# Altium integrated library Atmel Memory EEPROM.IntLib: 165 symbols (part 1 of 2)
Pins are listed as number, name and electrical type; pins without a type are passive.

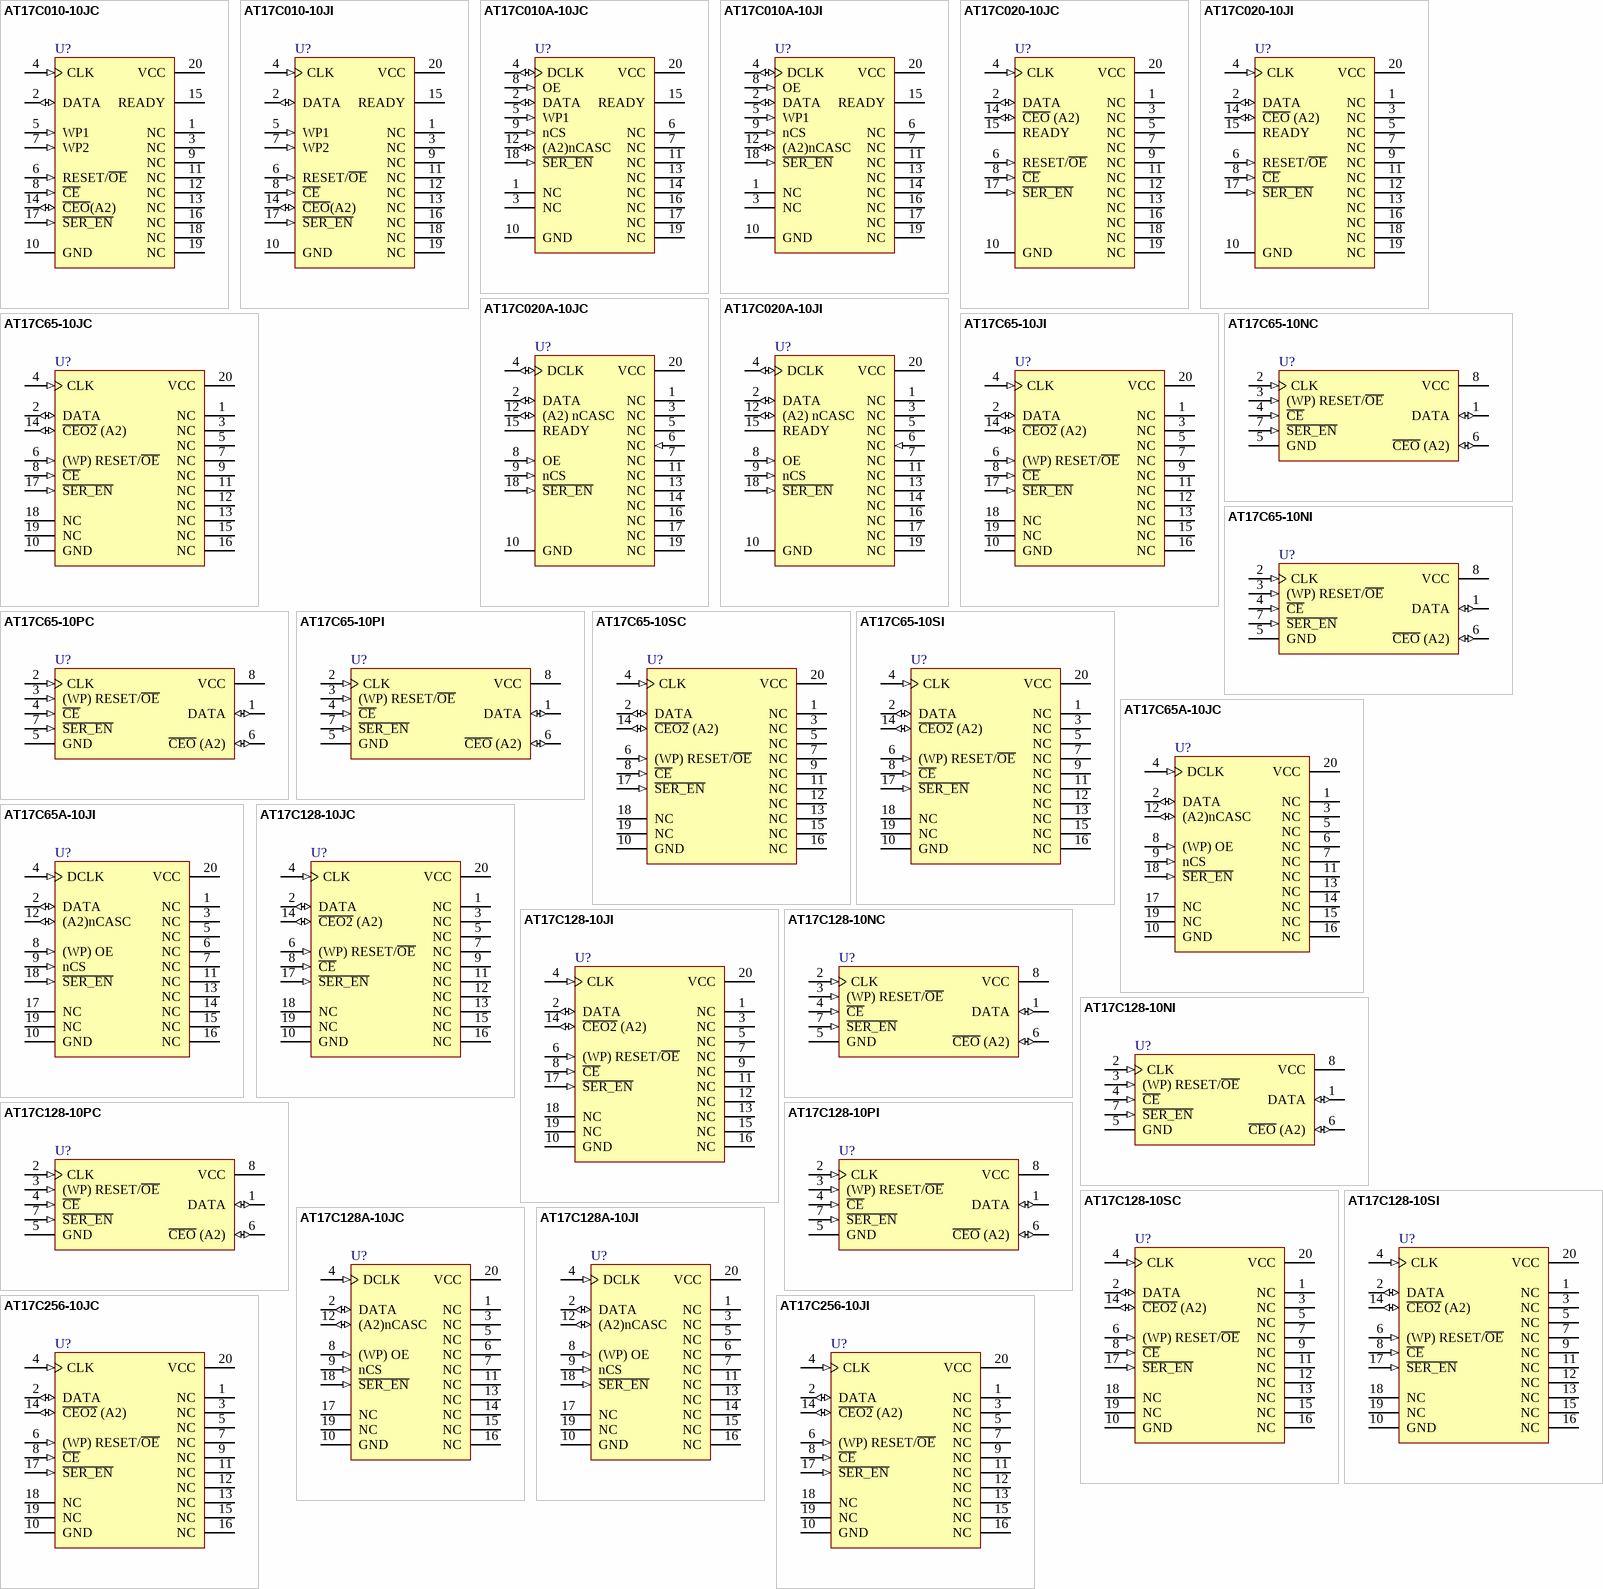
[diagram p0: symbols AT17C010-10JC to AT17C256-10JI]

## AT17C010-10JC
designator U?
FPGA Configuration EEPROM 1M Memory; ComponentAvailability: Not Recommended for New Design
footprint 20J_N (Leaded Chip Carrier, 20-Leads, Body 9x9mm, Pitch 1.27mm, IPC Medium Density)
footprint 20J_L (Leaded Chip Carrier, 20-Leads, Body 9x9mm, Pitch 1.27mm, IPC High Density)
footprint 20J_M (Leaded Chip Carrier, 20-Leads, Body 9x9mm, Pitch 1.27mm, IPC Low Density)
pins: 1 NC, 2 DATA (io), 3 NC, 4 CLK (in), 5 WP1 (in), 6 RESET/~{OE} (in), 7 WP2 (in), 8 ~{CE} (in), 9 NC, 10 GND (power), 11 NC, 12 NC, 13 NC, 14 ~{CEO}(A2) (io), 15 READY (oc), 16 NC, 17 ~{SER_EN} (in), 18 NC, 19 NC, 20 VCC (power)

## AT17C010-10JI
designator U?
FPGA Configuration EEPROM 1M Memory; ComponentAvailability: Not Recommended for New Design
footprint 20J_N (Leaded Chip Carrier, 20-Leads, Body 9x9mm, Pitch 1.27mm, IPC Medium Density)
footprint 20J_L (Leaded Chip Carrier, 20-Leads, Body 9x9mm, Pitch 1.27mm, IPC High Density)
footprint 20J_M (Leaded Chip Carrier, 20-Leads, Body 9x9mm, Pitch 1.27mm, IPC Low Density)
pins: 1 NC, 2 DATA (io), 3 NC, 4 CLK (in), 5 WP1 (in), 6 RESET/~{OE} (in), 7 WP2 (in), 8 ~{CE} (in), 9 NC, 10 GND (power), 11 NC, 12 NC, 13 NC, 14 ~{CEO}(A2) (io), 15 READY (oc), 16 NC, 17 ~{SER_EN} (in), 18 NC, 19 NC, 20 VCC (power)

## AT17C010A-10JC
designator U?
FPGA Configuration EEPROM  1M Memory; ComponentAvailability: Not Recommended for New Design
footprint 20J_N (Leaded Chip Carrier, 20-Leads, Body 9x9mm, Pitch 1.27mm, IPC Medium Density)
footprint 20J_L (Leaded Chip Carrier, 20-Leads, Body 9x9mm, Pitch 1.27mm, IPC High Density)
footprint 20J_M (Leaded Chip Carrier, 20-Leads, Body 9x9mm, Pitch 1.27mm, IPC Low Density)
pins: 1 NC, 2 DATA (io), 3 NC, 4 DCLK (io), 5 WP1 (in), 6 NC, 7 NC, 8 OE (in), 9 nCS (in), 10 GND (power), 11 NC, 12 (A2)nCASC (io), 13 NC, 14 NC, 15 READY (oc), 16 NC, 17 NC, 18 ~{SER_EN} (in), 19 NC, 20 VCC (power)

## AT17C010A-10JI
designator U?
FPGA Configuration EEPROM  1M Memory; ComponentAvailability: Not Recommended for New Design
footprint 20J_N (Leaded Chip Carrier, 20-Leads, Body 9x9mm, Pitch 1.27mm, IPC Medium Density)
footprint 20J_L (Leaded Chip Carrier, 20-Leads, Body 9x9mm, Pitch 1.27mm, IPC High Density)
footprint 20J_M (Leaded Chip Carrier, 20-Leads, Body 9x9mm, Pitch 1.27mm, IPC Low Density)
pins: 1 NC, 2 DATA (io), 3 NC, 4 DCLK (io), 5 WP1 (in), 6 NC, 7 NC, 8 OE (in), 9 nCS (in), 10 GND (power), 11 NC, 12 (A2)nCASC (io), 13 NC, 14 NC, 15 READY (oc), 16 NC, 17 NC, 18 ~{SER_EN} (in), 19 NC, 20 VCC (power)

## AT17C020-10JC
designator U?
FPGA Configuration EEPROM 2M Memory; ComponentAvailability: Not Recommended for New Design
footprint 20J_N (Leaded Chip Carrier, 20-Leads, Body 9x9mm, Pitch 1.27mm, IPC Medium Density)
footprint 20J_L (Leaded Chip Carrier, 20-Leads, Body 9x9mm, Pitch 1.27mm, IPC High Density)
footprint 20J_M (Leaded Chip Carrier, 20-Leads, Body 9x9mm, Pitch 1.27mm, IPC Low Density)
pins: 1 NC, 2 DATA (io), 3 NC, 4 CLK (in), 5 NC, 6 RESET/~{OE} (in), 7 NC, 8 ~{CE} (in), 9 NC, 10 GND (power), 11 NC, 12 NC, 13 NC, 14 ~{CEO} (A2) (io), 15 READY (oc), 16 NC, 17 ~{SER_EN} (in), 18 NC, 19 NC, 20 VCC (power)

## AT17C020-10JI
designator U?
FPGA Configuration EEPROM 2M Memory; ComponentAvailability: Not Recommended for New Design
footprint 20J_N (Leaded Chip Carrier, 20-Leads, Body 9x9mm, Pitch 1.27mm, IPC Medium Density)
footprint 20J_L (Leaded Chip Carrier, 20-Leads, Body 9x9mm, Pitch 1.27mm, IPC High Density)
footprint 20J_M (Leaded Chip Carrier, 20-Leads, Body 9x9mm, Pitch 1.27mm, IPC Low Density)
pins: 1 NC, 2 DATA (io), 3 NC, 4 CLK (in), 5 NC, 6 RESET/~{OE} (in), 7 NC, 8 ~{CE} (in), 9 NC, 10 GND (power), 11 NC, 12 NC, 13 NC, 14 ~{CEO} (A2) (io), 15 READY (oc), 16 NC, 17 ~{SER_EN} (in), 18 NC, 19 NC, 20 VCC (power)

## AT17C020A-10JC
designator U?
FPGA Configuration EEPROM 2M Memory; ComponentAvailability: Not Recommended for New Design
footprint 20J_N (Leaded Chip Carrier, 20-Leads, Body 9x9mm, Pitch 1.27mm, IPC Medium Density)
footprint 20J_L (Leaded Chip Carrier, 20-Leads, Body 9x9mm, Pitch 1.27mm, IPC High Density)
footprint 20J_M (Leaded Chip Carrier, 20-Leads, Body 9x9mm, Pitch 1.27mm, IPC Low Density)
pins: 1 NC, 2 DATA (io), 3 NC, 4 DCLK (io), 5 NC, 6 NC (in), 7 NC, 8 OE (in), 9 nCS (in), 10 GND (power), 11 NC, 12 (A2) nCASC (io), 13 NC, 14 NC, 15 READY (oc), 16 NC, 17 NC, 18 ~{SER_EN} (in), 19 NC, 20 VCC (power)

## AT17C020A-10JI
designator U?
FPGA Configuration EEPROM 2M Memory; ComponentAvailability: Not Recommended for New Design
footprint 20J_N (Leaded Chip Carrier, 20-Leads, Body 9x9mm, Pitch 1.27mm, IPC Medium Density)
footprint 20J_L (Leaded Chip Carrier, 20-Leads, Body 9x9mm, Pitch 1.27mm, IPC High Density)
footprint 20J_M (Leaded Chip Carrier, 20-Leads, Body 9x9mm, Pitch 1.27mm, IPC Low Density)
pins: 1 NC, 2 DATA (io), 3 NC, 4 DCLK (io), 5 NC, 6 NC (in), 7 NC, 8 OE (in), 9 nCS (in), 10 GND (power), 11 NC, 12 (A2) nCASC (io), 13 NC, 14 NC, 15 READY (oc), 16 NC, 17 NC, 18 ~{SER_EN} (in), 19 NC, 20 VCC (power)

## AT17C65-10JC
designator U?
FPGA Configuration EEPROM 64K Memory; ComponentAvailability: Not Recommended for New Design
footprint 20J_N (Leaded Chip Carrier, 20-Leads, Body 9x9mm, Pitch 1.27mm, IPC Medium Density)
footprint 20J_L (Leaded Chip Carrier, 20-Leads, Body 9x9mm, Pitch 1.27mm, IPC High Density)
footprint 20J_M (Leaded Chip Carrier, 20-Leads, Body 9x9mm, Pitch 1.27mm, IPC Low Density)
pins: 1 NC, 2 DATA (io), 3 NC, 4 CLK (in), 5 NC, 6 (WP) RESET/~{OE} (in), 7 NC, 8 ~{CE} (in), 9 NC, 10 GND (power), 11 NC, 12 NC, 13 NC, 14 ~{CEO2} (A2) (io), 15 NC, 16 NC, 17 ~{SER_EN} (in), 18 NC, 19 NC, 20 VCC (power)

## AT17C65-10JI
designator U?
FPGA Configuration EEPROM 64K Memory; ComponentAvailability: Not Recommended for New Design
footprint 20J_N (Leaded Chip Carrier, 20-Leads, Body 9x9mm, Pitch 1.27mm, IPC Medium Density)
footprint 20J_L (Leaded Chip Carrier, 20-Leads, Body 9x9mm, Pitch 1.27mm, IPC High Density)
footprint 20J_M (Leaded Chip Carrier, 20-Leads, Body 9x9mm, Pitch 1.27mm, IPC Low Density)
pins: 1 NC, 2 DATA (io), 3 NC, 4 CLK (in), 5 NC, 6 (WP) RESET/~{OE} (in), 7 NC, 8 ~{CE} (in), 9 NC, 10 GND (power), 11 NC, 12 NC, 13 NC, 14 ~{CEO2} (A2) (io), 15 NC, 16 NC, 17 ~{SER_EN} (in), 18 NC, 19 NC, 20 VCC (power)

## AT17C65-10NC
designator U?
FPGA Configuration EEPROM 64K Memory; ComponentAvailability: Not Recommended for New Design
footprint 8S1_N (SOIC, 8-Leads, Body 4.9x3.9mm, Pitch 1.27mm, IPC Medium Density)
footprint 8S1_L (SOIC, 8-Leads, Body 4.9x3.9mm, Pitch 1.27mm, IPC High Density)
footprint 8S1_M (SOIC, 8-Leads, Body 4.9x3.9mm, Pitch 1.27mm, IPC Low Density)
pins: 1 DATA (io), 2 CLK (in), 3 (WP) RESET/~{OE} (in), 4 ~{CE} (in), 5 GND (power), 6 ~{CEO} (A2) (io), 7 ~{SER_EN} (in), 8 VCC (power)

## AT17C65-10NI
designator U?
FPGA Configuration EEPROM 64K Memory; ComponentAvailability: Not Recommended for New Design
footprint 8S1_N (SOIC, 8-Leads, Body 4.9x3.9mm, Pitch 1.27mm, IPC Medium Density)
footprint 8S1_L (SOIC, 8-Leads, Body 4.9x3.9mm, Pitch 1.27mm, IPC High Density)
footprint 8S1_M (SOIC, 8-Leads, Body 4.9x3.9mm, Pitch 1.27mm, IPC Low Density)
pins: 1 DATA (io), 2 CLK (in), 3 (WP) RESET/~{OE} (in), 4 ~{CE} (in), 5 GND (power), 6 ~{CEO} (A2) (io), 7 ~{SER_EN} (in), 8 VCC (power)

## AT17C65-10PC
designator U?
FPGA Configuration EEPROM 64K Memory; ComponentAvailability: Not Recommended for New Design
footprint 8P3 (DIP, 8-Leads, Row Spacing 7.62mm, Pitch 2.54mm, Body 9.59x6.61mm)
pins: 1 DATA (io), 2 CLK (in), 3 (WP) RESET/~{OE} (in), 4 ~{CE} (in), 5 GND (power), 6 ~{CEO} (A2) (io), 7 ~{SER_EN} (in), 8 VCC (power)

## AT17C65-10PI
designator U?
FPGA Configuration EEPROM 64K Memory; ComponentAvailability: Not Recommended for New Design
footprint 8P3 (DIP, 8-Leads, Row Spacing 7.62mm, Pitch 2.54mm, Body 9.59x6.61mm)
pins: 1 DATA (io), 2 CLK (in), 3 (WP) RESET/~{OE} (in), 4 ~{CE} (in), 5 GND (power), 6 ~{CEO} (A2) (io), 7 ~{SER_EN} (in), 8 VCC (power)

## AT17C65-10SC
designator U?
FPGA Configuration EEPROM 64K Memory; ComponentAvailability: Not Recommended for New Design
footprint 20S_N (SOIC, 20-Leads, Body 12.8x7.5mm, Pitch 1.27mm, IPC Medium Density)
footprint 20S_L (SOIC, 20-Leads, Body 12.8x7.5mm, Pitch 1.27mm, IPC High Density)
footprint 20S_M (SOIC, 20-Leads, Body 12.8x7.5mm, Pitch 1.27mm, IPC Low Density)
pins: 1 NC, 2 DATA (io), 3 NC, 4 CLK (in), 5 NC, 6 (WP) RESET/~{OE} (in), 7 NC, 8 ~{CE} (in), 9 NC, 10 GND (power), 11 NC, 12 NC, 13 NC, 14 ~{CEO2} (A2) (io), 15 NC, 16 NC, 17 ~{SER_EN} (in), 18 NC, 19 NC, 20 VCC (power)

## AT17C65-10SI
designator U?
FPGA Configuration EEPROM 64K Memory; ComponentAvailability: Not Recommended for New Design
footprint 20S_N (SOIC, 20-Leads, Body 12.8x7.5mm, Pitch 1.27mm, IPC Medium Density)
footprint 20S_L (SOIC, 20-Leads, Body 12.8x7.5mm, Pitch 1.27mm, IPC High Density)
footprint 20S_M (SOIC, 20-Leads, Body 12.8x7.5mm, Pitch 1.27mm, IPC Low Density)
pins: 1 NC, 2 DATA (io), 3 NC, 4 CLK (in), 5 NC, 6 (WP) RESET/~{OE} (in), 7 NC, 8 ~{CE} (in), 9 NC, 10 GND (power), 11 NC, 12 NC, 13 NC, 14 ~{CEO2} (A2) (io), 15 NC, 16 NC, 17 ~{SER_EN} (in), 18 NC, 19 NC, 20 VCC (power)

## AT17C65A-10JC
designator U?
FPGA Configuration EEPROM 64K Memory; ComponentAvailability: Not Recommended for New Design
footprint 20J_N (Leaded Chip Carrier, 20-Leads, Body 9x9mm, Pitch 1.27mm, IPC Medium Density)
footprint 20J_L (Leaded Chip Carrier, 20-Leads, Body 9x9mm, Pitch 1.27mm, IPC High Density)
footprint 20J_M (Leaded Chip Carrier, 20-Leads, Body 9x9mm, Pitch 1.27mm, IPC Low Density)
pins: 1 NC, 2 DATA (io), 3 NC, 4 DCLK (in), 5 NC, 6 NC, 7 NC, 8 (WP) OE (in), 9 nCS (in), 10 GND (power), 11 NC, 12 (A2)nCASC (io), 13 NC, 14 NC, 15 NC, 16 NC, 17 NC, 18 ~{SER_EN} (in), 19 NC, 20 VCC (power)

## AT17C65A-10JI
designator U?
FPGA Configuration EEPROM 64K Memory; ComponentAvailability: Not Recommended for New Design
footprint 20J_N (Leaded Chip Carrier, 20-Leads, Body 9x9mm, Pitch 1.27mm, IPC Medium Density)
footprint 20J_L (Leaded Chip Carrier, 20-Leads, Body 9x9mm, Pitch 1.27mm, IPC High Density)
footprint 20J_M (Leaded Chip Carrier, 20-Leads, Body 9x9mm, Pitch 1.27mm, IPC Low Density)
pins: 1 NC, 2 DATA (io), 3 NC, 4 DCLK (in), 5 NC, 6 NC, 7 NC, 8 (WP) OE (in), 9 nCS (in), 10 GND (power), 11 NC, 12 (A2)nCASC (io), 13 NC, 14 NC, 15 NC, 16 NC, 17 NC, 18 ~{SER_EN} (in), 19 NC, 20 VCC (power)

## AT17C128-10JC
designator U?
FPGA Configuration EEPROM 128K Memory; ComponentAvailability: Not Recommended for New Design
footprint 20J_N (Leaded Chip Carrier, 20-Leads, Body 9x9mm, Pitch 1.27mm, IPC Medium Density)
footprint 20J_L (Leaded Chip Carrier, 20-Leads, Body 9x9mm, Pitch 1.27mm, IPC High Density)
footprint 20J_M (Leaded Chip Carrier, 20-Leads, Body 9x9mm, Pitch 1.27mm, IPC Low Density)
pins: 1 NC, 2 DATA (io), 3 NC, 4 CLK (in), 5 NC, 6 (WP) RESET/~{OE} (in), 7 NC, 8 ~{CE} (in), 9 NC, 10 GND (power), 11 NC, 12 NC, 13 NC, 14 ~{CEO2} (A2) (io), 15 NC, 16 NC, 17 ~{SER_EN} (in), 18 NC, 19 NC, 20 VCC (power)

## AT17C128-10JI
designator U?
FPGA Configuration EEPROM 128K Memory; ComponentAvailability: Not Recommended for New Design
footprint 20J_N (Leaded Chip Carrier, 20-Leads, Body 9x9mm, Pitch 1.27mm, IPC Medium Density)
footprint 20J_L (Leaded Chip Carrier, 20-Leads, Body 9x9mm, Pitch 1.27mm, IPC High Density)
footprint 20J_M (Leaded Chip Carrier, 20-Leads, Body 9x9mm, Pitch 1.27mm, IPC Low Density)
pins: 1 NC, 2 DATA (io), 3 NC, 4 CLK (in), 5 NC, 6 (WP) RESET/~{OE} (in), 7 NC, 8 ~{CE} (in), 9 NC, 10 GND (power), 11 NC, 12 NC, 13 NC, 14 ~{CEO2} (A2) (io), 15 NC, 16 NC, 17 ~{SER_EN} (in), 18 NC, 19 NC, 20 VCC (power)

## AT17C128-10NC
designator U?
FPGA Configuration EEPROM 128K Memory; ComponentAvailability: Not Recommended for New Design
footprint 8S1_N (SOIC, 8-Leads, Body 4.9x3.9mm, Pitch 1.27mm, IPC Medium Density)
footprint 8S1_L (SOIC, 8-Leads, Body 4.9x3.9mm, Pitch 1.27mm, IPC High Density)
footprint 8S1_M (SOIC, 8-Leads, Body 4.9x3.9mm, Pitch 1.27mm, IPC Low Density)
pins: 1 DATA (io), 2 CLK (in), 3 (WP) RESET/~{OE} (in), 4 ~{CE} (in), 5 GND (power), 6 ~{CEO} (A2) (io), 7 ~{SER_EN} (in), 8 VCC (power)

## AT17C128-10NI
designator U?
FPGA Configuration EEPROM 128K Memory; ComponentAvailability: Not Recommended for New Design
footprint 8S1_N (SOIC, 8-Leads, Body 4.9x3.9mm, Pitch 1.27mm, IPC Medium Density)
footprint 8S1_L (SOIC, 8-Leads, Body 4.9x3.9mm, Pitch 1.27mm, IPC High Density)
footprint 8S1_M (SOIC, 8-Leads, Body 4.9x3.9mm, Pitch 1.27mm, IPC Low Density)
pins: 1 DATA (io), 2 CLK (in), 3 (WP) RESET/~{OE} (in), 4 ~{CE} (in), 5 GND (power), 6 ~{CEO} (A2) (io), 7 ~{SER_EN} (in), 8 VCC (power)

## AT17C128-10PC
designator U?
FPGA Configuration EEPROM 128K Memory; ComponentAvailability: Not Recommended for New Design
footprint 8P3 (DIP, 8-Leads, Row Spacing 7.62mm, Pitch 2.54mm, Body 9.59x6.61mm)
pins: 1 DATA (io), 2 CLK (in), 3 (WP) RESET/~{OE} (in), 4 ~{CE} (in), 5 GND (power), 6 ~{CEO} (A2) (io), 7 ~{SER_EN} (in), 8 VCC (power)

## AT17C128-10PI
designator U?
FPGA Configuration EEPROM 128K Memory; ComponentAvailability: Not Recommended for New Design
footprint 8P3 (DIP, 8-Leads, Row Spacing 7.62mm, Pitch 2.54mm, Body 9.59x6.61mm)
pins: 1 DATA (io), 2 CLK (in), 3 (WP) RESET/~{OE} (in), 4 ~{CE} (in), 5 GND (power), 6 ~{CEO} (A2) (io), 7 ~{SER_EN} (in), 8 VCC (power)

## AT17C128-10SC
designator U?
FPGA Configuration EEPROM 128K Memory; ComponentAvailability: Not Recommended for New Design
footprint 20S_N (SOIC, 20-Leads, Body 12.8x7.5mm, Pitch 1.27mm, IPC Medium Density)
footprint 20S_L (SOIC, 20-Leads, Body 12.8x7.5mm, Pitch 1.27mm, IPC High Density)
footprint 20S_M (SOIC, 20-Leads, Body 12.8x7.5mm, Pitch 1.27mm, IPC Low Density)
pins: 1 NC, 2 DATA (io), 3 NC, 4 CLK (in), 5 NC, 6 (WP) RESET/~{OE} (in), 7 NC, 8 ~{CE} (in), 9 NC, 10 GND (power), 11 NC, 12 NC, 13 NC, 14 ~{CEO2} (A2) (io), 15 NC, 16 NC, 17 ~{SER_EN} (in), 18 NC, 19 NC, 20 VCC (power)

## AT17C128-10SI
designator U?
FPGA Configuration EEPROM 128K Memory; ComponentAvailability: Not Recommended for New Design
footprint 20S_N (SOIC, 20-Leads, Body 12.8x7.5mm, Pitch 1.27mm, IPC Medium Density)
footprint 20S_L (SOIC, 20-Leads, Body 12.8x7.5mm, Pitch 1.27mm, IPC High Density)
footprint 20S_M (SOIC, 20-Leads, Body 12.8x7.5mm, Pitch 1.27mm, IPC Low Density)
pins: 1 NC, 2 DATA (io), 3 NC, 4 CLK (in), 5 NC, 6 (WP) RESET/~{OE} (in), 7 NC, 8 ~{CE} (in), 9 NC, 10 GND (power), 11 NC, 12 NC, 13 NC, 14 ~{CEO2} (A2) (io), 15 NC, 16 NC, 17 ~{SER_EN} (in), 18 NC, 19 NC, 20 VCC (power)

## AT17C128A-10JC
designator U?
FPGA Configuration EEPROM 128K Memory; ComponentAvailability: Not Recommended for New Design
footprint 20J_N (Leaded Chip Carrier, 20-Leads, Body 9x9mm, Pitch 1.27mm, IPC Medium Density)
footprint 20J_L (Leaded Chip Carrier, 20-Leads, Body 9x9mm, Pitch 1.27mm, IPC High Density)
footprint 20J_M (Leaded Chip Carrier, 20-Leads, Body 9x9mm, Pitch 1.27mm, IPC Low Density)
pins: 1 NC, 2 DATA (io), 3 NC, 4 DCLK (in), 5 NC, 6 NC, 7 NC, 8 (WP) OE (in), 9 nCS (in), 10 GND (power), 11 NC, 12 (A2)nCASC (io), 13 NC, 14 NC, 15 NC, 16 NC, 17 NC, 18 ~{SER_EN} (in), 19 NC, 20 VCC (power)

## AT17C128A-10JI
designator U?
FPGA Configuration EEPROM 128K Memory; ComponentAvailability: Not Recommended for New Design
footprint 20J_N (Leaded Chip Carrier, 20-Leads, Body 9x9mm, Pitch 1.27mm, IPC Medium Density)
footprint 20J_L (Leaded Chip Carrier, 20-Leads, Body 9x9mm, Pitch 1.27mm, IPC High Density)
footprint 20J_M (Leaded Chip Carrier, 20-Leads, Body 9x9mm, Pitch 1.27mm, IPC Low Density)
pins: 1 NC, 2 DATA (io), 3 NC, 4 DCLK (in), 5 NC, 6 NC, 7 NC, 8 (WP) OE (in), 9 nCS (in), 10 GND (power), 11 NC, 12 (A2)nCASC (io), 13 NC, 14 NC, 15 NC, 16 NC, 17 NC, 18 ~{SER_EN} (in), 19 NC, 20 VCC (power)

## AT17C256-10JC
designator U?
FPGA Configuration EEPROM 256K Memory; ComponentAvailability: Not Recommended for New Design
footprint 20J_N (Leaded Chip Carrier, 20-Leads, Body 9x9mm, Pitch 1.27mm, IPC Medium Density)
footprint 20J_L (Leaded Chip Carrier, 20-Leads, Body 9x9mm, Pitch 1.27mm, IPC High Density)
footprint 20J_M (Leaded Chip Carrier, 20-Leads, Body 9x9mm, Pitch 1.27mm, IPC Low Density)
pins: 1 NC, 2 DATA (io), 3 NC, 4 CLK (in), 5 NC, 6 (WP) RESET/~{OE} (in), 7 NC, 8 ~{CE} (in), 9 NC, 10 GND (power), 11 NC, 12 NC, 13 NC, 14 ~{CEO2} (A2) (io), 15 NC, 16 NC, 17 ~{SER_EN} (in), 18 NC, 19 NC, 20 VCC (power)

## AT17C256-10JI
designator U?
FPGA Configuration EEPROM 256K Memory; ComponentAvailability: Not Recommended for New Design
footprint 20J_N (Leaded Chip Carrier, 20-Leads, Body 9x9mm, Pitch 1.27mm, IPC Medium Density)
footprint 20J_L (Leaded Chip Carrier, 20-Leads, Body 9x9mm, Pitch 1.27mm, IPC High Density)
footprint 20J_M (Leaded Chip Carrier, 20-Leads, Body 9x9mm, Pitch 1.27mm, IPC Low Density)
pins: 1 NC, 2 DATA (io), 3 NC, 4 CLK (in), 5 NC, 6 (WP) RESET/~{OE} (in), 7 NC, 8 ~{CE} (in), 9 NC, 10 GND (power), 11 NC, 12 NC, 13 NC, 14 ~{CEO2} (A2) (io), 15 NC, 16 NC, 17 ~{SER_EN} (in), 18 NC, 19 NC, 20 VCC (power)

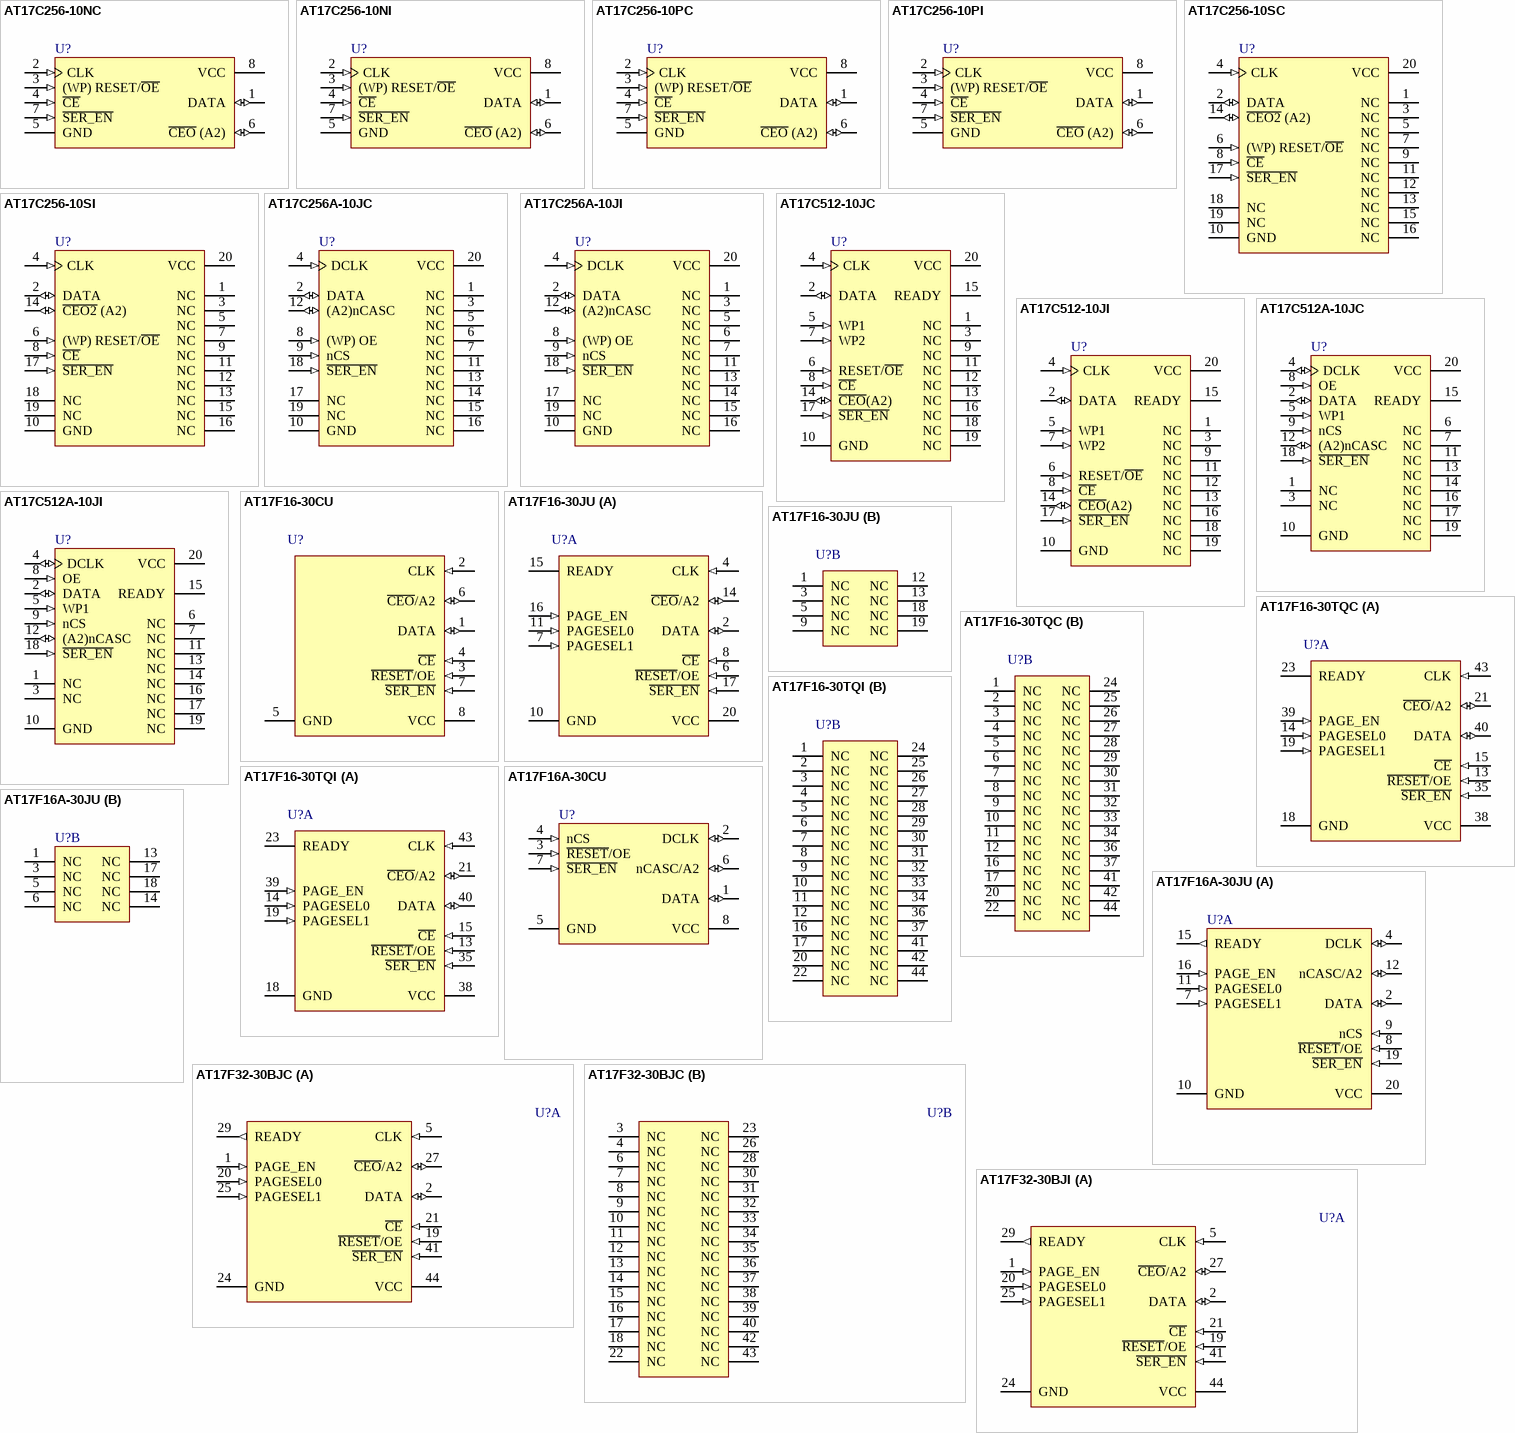
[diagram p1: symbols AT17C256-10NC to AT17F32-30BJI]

## AT17C256-10NC
designator U?
FPGA Configuration EEPROM 256K Memory; ComponentAvailability: Not Recommended for New Design
footprint 8S1_N (SOIC, 8-Leads, Body 4.9x3.9mm, Pitch 1.27mm, IPC Medium Density)
footprint 8S1_L (SOIC, 8-Leads, Body 4.9x3.9mm, Pitch 1.27mm, IPC High Density)
footprint 8S1_M (SOIC, 8-Leads, Body 4.9x3.9mm, Pitch 1.27mm, IPC Low Density)
pins: 1 DATA (io), 2 CLK (in), 3 (WP) RESET/~{OE} (in), 4 ~{CE} (in), 5 GND (power), 6 ~{CEO} (A2) (io), 7 ~{SER_EN} (in), 8 VCC (power)

## AT17C256-10NI
designator U?
FPGA Configuration EEPROM 256K Memory; ComponentAvailability: Not Recommended for New Design
footprint 8S1_N (SOIC, 8-Leads, Body 4.9x3.9mm, Pitch 1.27mm, IPC Medium Density)
footprint 8S1_L (SOIC, 8-Leads, Body 4.9x3.9mm, Pitch 1.27mm, IPC High Density)
footprint 8S1_M (SOIC, 8-Leads, Body 4.9x3.9mm, Pitch 1.27mm, IPC Low Density)
pins: 1 DATA (io), 2 CLK (in), 3 (WP) RESET/~{OE} (in), 4 ~{CE} (in), 5 GND (power), 6 ~{CEO} (A2) (io), 7 ~{SER_EN} (in), 8 VCC (power)

## AT17C256-10PC
designator U?
FPGA Configuration EEPROM 256K Memory; ComponentAvailability: Not Recommended for New Design
footprint 8P3 (DIP, 8-Leads, Row Spacing 7.62mm, Pitch 2.54mm, Body 9.59x6.61mm)
pins: 1 DATA (io), 2 CLK (in), 3 (WP) RESET/~{OE} (in), 4 ~{CE} (in), 5 GND (power), 6 ~{CEO} (A2) (io), 7 ~{SER_EN} (in), 8 VCC (power)

## AT17C256-10PI
designator U?
FPGA Configuration EEPROM 256K Memory; ComponentAvailability: Not Recommended for New Design
footprint 8P3 (DIP, 8-Leads, Row Spacing 7.62mm, Pitch 2.54mm, Body 9.59x6.61mm)
pins: 1 DATA (io), 2 CLK (in), 3 (WP) RESET/~{OE} (in), 4 ~{CE} (in), 5 GND (power), 6 ~{CEO} (A2) (io), 7 ~{SER_EN} (in), 8 VCC (power)

## AT17C256-10SC
designator U?
FPGA Configuration EEPROM 256K Memory; ComponentAvailability: Not Recommended for New Design
footprint 20S_N (SOIC, 20-Leads, Body 12.8x7.5mm, Pitch 1.27mm, IPC Medium Density)
footprint 20S_L (SOIC, 20-Leads, Body 12.8x7.5mm, Pitch 1.27mm, IPC High Density)
footprint 20S_M (SOIC, 20-Leads, Body 12.8x7.5mm, Pitch 1.27mm, IPC Low Density)
pins: 1 NC, 2 DATA (io), 3 NC, 4 CLK (in), 5 NC, 6 (WP) RESET/~{OE} (in), 7 NC, 8 ~{CE} (in), 9 NC, 10 GND (power), 11 NC, 12 NC, 13 NC, 14 ~{CEO2} (A2) (io), 15 NC, 16 NC, 17 ~{SER_EN} (in), 18 NC, 19 NC, 20 VCC (power)

## AT17C256-10SI
designator U?
FPGA Configuration EEPROM 256K Memory; ComponentAvailability: Not Recommended for New Design
footprint 20S_N (SOIC, 20-Leads, Body 12.8x7.5mm, Pitch 1.27mm, IPC Medium Density)
footprint 20S_L (SOIC, 20-Leads, Body 12.8x7.5mm, Pitch 1.27mm, IPC High Density)
footprint 20S_M (SOIC, 20-Leads, Body 12.8x7.5mm, Pitch 1.27mm, IPC Low Density)
pins: 1 NC, 2 DATA (io), 3 NC, 4 CLK (in), 5 NC, 6 (WP) RESET/~{OE} (in), 7 NC, 8 ~{CE} (in), 9 NC, 10 GND (power), 11 NC, 12 NC, 13 NC, 14 ~{CEO2} (A2) (io), 15 NC, 16 NC, 17 ~{SER_EN} (in), 18 NC, 19 NC, 20 VCC (power)

## AT17C256A-10JC
designator U?
FPGA Configuration EEPROM 256K Memory; ComponentAvailability: Not Recommended for New Design
footprint 20J_N (Leaded Chip Carrier, 20-Leads, Body 9x9mm, Pitch 1.27mm, IPC Medium Density)
footprint 20J_L (Leaded Chip Carrier, 20-Leads, Body 9x9mm, Pitch 1.27mm, IPC High Density)
footprint 20J_M (Leaded Chip Carrier, 20-Leads, Body 9x9mm, Pitch 1.27mm, IPC Low Density)
pins: 1 NC, 2 DATA (io), 3 NC, 4 DCLK (in), 5 NC, 6 NC, 7 NC, 8 (WP) OE (in), 9 nCS (in), 10 GND (power), 11 NC, 12 (A2)nCASC (io), 13 NC, 14 NC, 15 NC, 16 NC, 17 NC, 18 ~{SER_EN} (in), 19 NC, 20 VCC (power)

## AT17C256A-10JI
designator U?
FPGA Configuration EEPROM 256K Memory; ComponentAvailability: Not Recommended for New Design
footprint 20J_N (Leaded Chip Carrier, 20-Leads, Body 9x9mm, Pitch 1.27mm, IPC Medium Density)
footprint 20J_L (Leaded Chip Carrier, 20-Leads, Body 9x9mm, Pitch 1.27mm, IPC High Density)
footprint 20J_M (Leaded Chip Carrier, 20-Leads, Body 9x9mm, Pitch 1.27mm, IPC Low Density)
pins: 1 NC, 2 DATA (io), 3 NC, 4 DCLK (in), 5 NC, 6 NC, 7 NC, 8 (WP) OE (in), 9 nCS (in), 10 GND (power), 11 NC, 12 (A2)nCASC (io), 13 NC, 14 NC, 15 NC, 16 NC, 17 NC, 18 ~{SER_EN} (in), 19 NC, 20 VCC (power)

## AT17C512-10JC
designator U?
FPGA Configuration EEPROM 512K Memory; ComponentAvailability: Not Recommended for New Design
footprint 20J_N (Leaded Chip Carrier, 20-Leads, Body 9x9mm, Pitch 1.27mm, IPC Medium Density)
footprint 20J_L (Leaded Chip Carrier, 20-Leads, Body 9x9mm, Pitch 1.27mm, IPC High Density)
footprint 20J_M (Leaded Chip Carrier, 20-Leads, Body 9x9mm, Pitch 1.27mm, IPC Low Density)
pins: 1 NC, 2 DATA (io), 3 NC, 4 CLK (in), 5 WP1 (in), 6 RESET/~{OE} (in), 7 WP2 (in), 8 ~{CE} (in), 9 NC, 10 GND (power), 11 NC, 12 NC, 13 NC, 14 ~{CEO}(A2) (io), 15 READY (oc), 16 NC, 17 ~{SER_EN} (in), 18 NC, 19 NC, 20 VCC (power)

## AT17C512-10JI
designator U?
FPGA Configuration EEPROM 512K Memory; ComponentAvailability: Not Recommended for New Design
footprint 20J_N (Leaded Chip Carrier, 20-Leads, Body 9x9mm, Pitch 1.27mm, IPC Medium Density)
footprint 20J_L (Leaded Chip Carrier, 20-Leads, Body 9x9mm, Pitch 1.27mm, IPC High Density)
footprint 20J_M (Leaded Chip Carrier, 20-Leads, Body 9x9mm, Pitch 1.27mm, IPC Low Density)
pins: 1 NC, 2 DATA (io), 3 NC, 4 CLK (in), 5 WP1 (in), 6 RESET/~{OE} (in), 7 WP2 (in), 8 ~{CE} (in), 9 NC, 10 GND (power), 11 NC, 12 NC, 13 NC, 14 ~{CEO}(A2) (io), 15 READY (oc), 16 NC, 17 ~{SER_EN} (in), 18 NC, 19 NC, 20 VCC (power)

## AT17C512A-10JC
designator U?
FPGA Configuration EEPROM 512K Memory; ComponentAvailability: Not Recommended for New Design
footprint 20J_N (Leaded Chip Carrier, 20-Leads, Body 9x9mm, Pitch 1.27mm, IPC Medium Density)
footprint 20J_L (Leaded Chip Carrier, 20-Leads, Body 9x9mm, Pitch 1.27mm, IPC High Density)
footprint 20J_M (Leaded Chip Carrier, 20-Leads, Body 9x9mm, Pitch 1.27mm, IPC Low Density)
pins: 1 NC, 2 DATA (io), 3 NC, 4 DCLK (io), 5 WP1 (in), 6 NC, 7 NC, 8 OE (in), 9 nCS (in), 10 GND (power), 11 NC, 12 (A2)nCASC (io), 13 NC, 14 NC, 15 READY (oc), 16 NC, 17 NC, 18 ~{SER_EN} (in), 19 NC, 20 VCC (power)

## AT17C512A-10JI
designator U?
FPGA Configuration EEPROM  512K Memory; ComponentAvailability: Not Recommended for New Design
footprint 20J_N (Leaded Chip Carrier, 20-Leads, Body 9x9mm, Pitch 1.27mm, IPC Medium Density)
footprint 20J_L (Leaded Chip Carrier, 20-Leads, Body 9x9mm, Pitch 1.27mm, IPC High Density)
footprint 20J_M (Leaded Chip Carrier, 20-Leads, Body 9x9mm, Pitch 1.27mm, IPC Low Density)
pins: 1 NC, 2 DATA (io), 3 NC, 4 DCLK (io), 5 WP1 (in), 6 NC, 7 NC, 8 OE (in), 9 nCS (in), 10 GND (power), 11 NC, 12 (A2)nCASC (io), 13 NC, 14 NC, 15 READY (oc), 16 NC, 17 NC, 18 ~{SER_EN} (in), 19 NC, 20 VCC (power)

## AT17F16-30CU
designator U?
FPGA Configuration Flash Memory, 16-MBit Memory, 8-Pin LAP, Industrial Grade (-40°C to 85°C), Pb-Free
footprint 8CN4 (SON, 8-Leads, Body 6x6 mm, Pitch 1.27mm)
pins: 1 DATA (io), 2 CLK (in), 3 ~{RESET}/OE (in), 4 ~{CE} (in), 5 GND (power), 6 ~{CEO}/A2 (io), 7 ~{SER_EN} (in), 8 VCC (power)

## AT17F16-30JU
designator U?
FPGA Configuration Flash Memory, 16-MBit Memory, 20-Pin PLCC, Industrial Grade (-40°C to 85°C), Pb-Free
footprint 20J_N (Leaded Chip Carrier, 20-Leads, Body 9x9mm, Pitch 1.27mm, IPC Medium Density)
footprint 20J_L (Leaded Chip Carrier, 20-Leads, Body 9x9mm, Pitch 1.27mm, IPC High Density)
footprint 20J_M (Leaded Chip Carrier, 20-Leads, Body 9x9mm, Pitch 1.27mm, IPC Low Density)
part A pins: 2 DATA (io), 4 CLK (in), 6 ~{RESET}/OE (in), 7 PAGESEL1 (in), 8 ~{CE} (in), 10 GND (power), 11 PAGESEL0 (in), 14 ~{CEO}/A2 (io), 15 READY (oc), 16 PAGE_EN (in), 17 ~{SER_EN} (in), 20 VCC (power)
part B pins: 1 NC, 3 NC, 5 NC, 9 NC, 12 NC, 13 NC, 18 NC, 19 NC

## AT17F16-30TQC
designator U?
FPGA Configuration Flash Memory, 16-MBit Memory, 44-Pin TQFP, Commercial Grade (0°C to 70°C)
footprint 44A_N (Thin QFP, 44-Leads, Body 10x10mm, Pitch 0.8mm, IPC Medium Density)
footprint 44A_L (Thin QFP, 44-Leads, Body 10x10mm, Pitch 0.8mm, IPC High Density)
footprint 44A_M (Thin QFP, 44-Leads, Body 10x10mm, Pitch 0.8mm, IPC Low Density)
part A pins: 13 ~{RESET}/OE (in), 14 PAGESEL0 (in), 15 ~{CE} (in), 18 GND (power), 19 PAGESEL1 (in), 21 ~{CEO}/A2 (io), 23 READY (oc), 35 ~{SER_EN} (in), 38 VCC (power), 39 PAGE_EN (in), 40 DATA (io), 43 CLK (in)
part B pins: 1 NC, 2 NC, 3 NC, 4 NC, 5 NC, 6 NC, 7 NC, 8 NC, 9 NC, 10 NC, 11 NC, 12 NC, 16 NC, 17 NC, 20 NC, 22 NC, 24 NC, 25 NC, 26 NC, 27 NC, 28 NC, 29 NC, 30 NC, 31 NC, 32 NC, 33 NC, 34 NC, 36 NC, 37 NC, 41 NC, 42 NC, 44 NC

## AT17F16-30TQI
designator U?
FPGA Configuration Flash Memory, 16-MBit Memory, 44-Pin TQFP, Industrial Grade (-40°C to 85°C)
footprint 44A_N (Thin QFP, 44-Leads, Body 10x10mm, Pitch 0.8mm, IPC Medium Density)
footprint 44A_L (Thin QFP, 44-Leads, Body 10x10mm, Pitch 0.8mm, IPC High Density)
footprint 44A_M (Thin QFP, 44-Leads, Body 10x10mm, Pitch 0.8mm, IPC Low Density)
part A pins: 13 ~{RESET}/OE (in), 14 PAGESEL0 (in), 15 ~{CE} (in), 18 GND (power), 19 PAGESEL1 (in), 21 ~{CEO}/A2 (io), 23 READY (oc), 35 ~{SER_EN} (in), 38 VCC (power), 39 PAGE_EN (in), 40 DATA (io), 43 CLK (in)
part B pins: 1 NC, 2 NC, 3 NC, 4 NC, 5 NC, 6 NC, 7 NC, 8 NC, 9 NC, 10 NC, 11 NC, 12 NC, 16 NC, 17 NC, 20 NC, 22 NC, 24 NC, 25 NC, 26 NC, 27 NC, 28 NC, 29 NC, 30 NC, 31 NC, 32 NC, 33 NC, 34 NC, 36 NC, 37 NC, 41 NC, 42 NC, 44 NC

## AT17F16A-30CU
designator U?
FPGA Configuration Flash Memory, 16-Mbit Memory, 8-Pin LAP, Industrial Grade (-40°C to 85°C)
footprint 8CN4 (SON, 8-Leads, Body 6x6 mm, Pitch 1.27mm)
pins: 1 DATA (io), 2 DCLK (io), 3 ~{RESET}/OE (in), 4 nCS (in), 5 GND (power), 6 nCASC/A2 (io), 7 ~{SER_EN} (in), 8 VCC (power)

## AT17F16A-30JU
designator U?
FPGA Configuration Flash Memory, 16-Mbit Memory, 20-Pin PLCC, Industrial Grade (-40°C to 85°C)
footprint 20J_N (Leaded Chip Carrier, 20-Leads, Body 9x9mm, Pitch 1.27mm, IPC Medium Density)
footprint 20J_L (Leaded Chip Carrier, 20-Leads, Body 9x9mm, Pitch 1.27mm, IPC High Density)
footprint 20J_M (Leaded Chip Carrier, 20-Leads, Body 9x9mm, Pitch 1.27mm, IPC Low Density)
part A pins: 2 DATA (io), 4 DCLK (io), 7 PAGESEL1 (in), 8 ~{RESET}/OE (in), 9 nCS (in), 10 GND (power), 11 PAGESEL0 (in), 12 nCASC/A2 (io), 15 READY (out), 16 PAGE_EN (in), 19 ~{SER_EN} (in), 20 VCC (power)
part B pins: 1 NC, 3 NC, 5 NC, 6 NC, 13 NC, 14 NC, 17 NC, 18 NC

## AT17F32-30BJC
designator U?
FPGA Configuration Flash Memory, 32-MBit Memory, 44-Pin PLCC, Commercial Grade
footprint 44J_N (Leaded Chip Carrier, 44-Leads, Body 16.6x16.6mm, Pitch 1.27mm, IPC Medium Density)
footprint 44J_L (Leaded Chip Carrier, 44-Leads, Body 16.6x16.6mm, Pitch 1.27mm, IPC High Density)
footprint 44J_M (Leaded Chip Carrier, 44-Leads, Body 16.6x16.6mm, Pitch 1.27mm, IPC Low Density)
part A pins: 1 PAGE_EN (in), 2 DATA (io), 5 CLK (in), 19 ~{RESET}/OE (in), 20 PAGESEL0 (in), 21 ~{CE} (in), 24 GND (power), 25 PAGESEL1 (in), 27 ~{CEO}/A2 (io), 29 READY (out), 41 ~{SER_EN} (in), 44 VCC (power)
part B pins: 3 NC, 4 NC, 6 NC, 7 NC, 8 NC, 9 NC, 10 NC, 11 NC, 12 NC, 13 NC, 14 NC, 15 NC, 16 NC, 17 NC, 18 NC, 22 NC, 23 NC, 26 NC, 28 NC, 30 NC, 31 NC, 32 NC, 33 NC, 34 NC, 35 NC, 36 NC, 37 NC, 38 NC, 39 NC, 40 NC, 42 NC, 43 NC

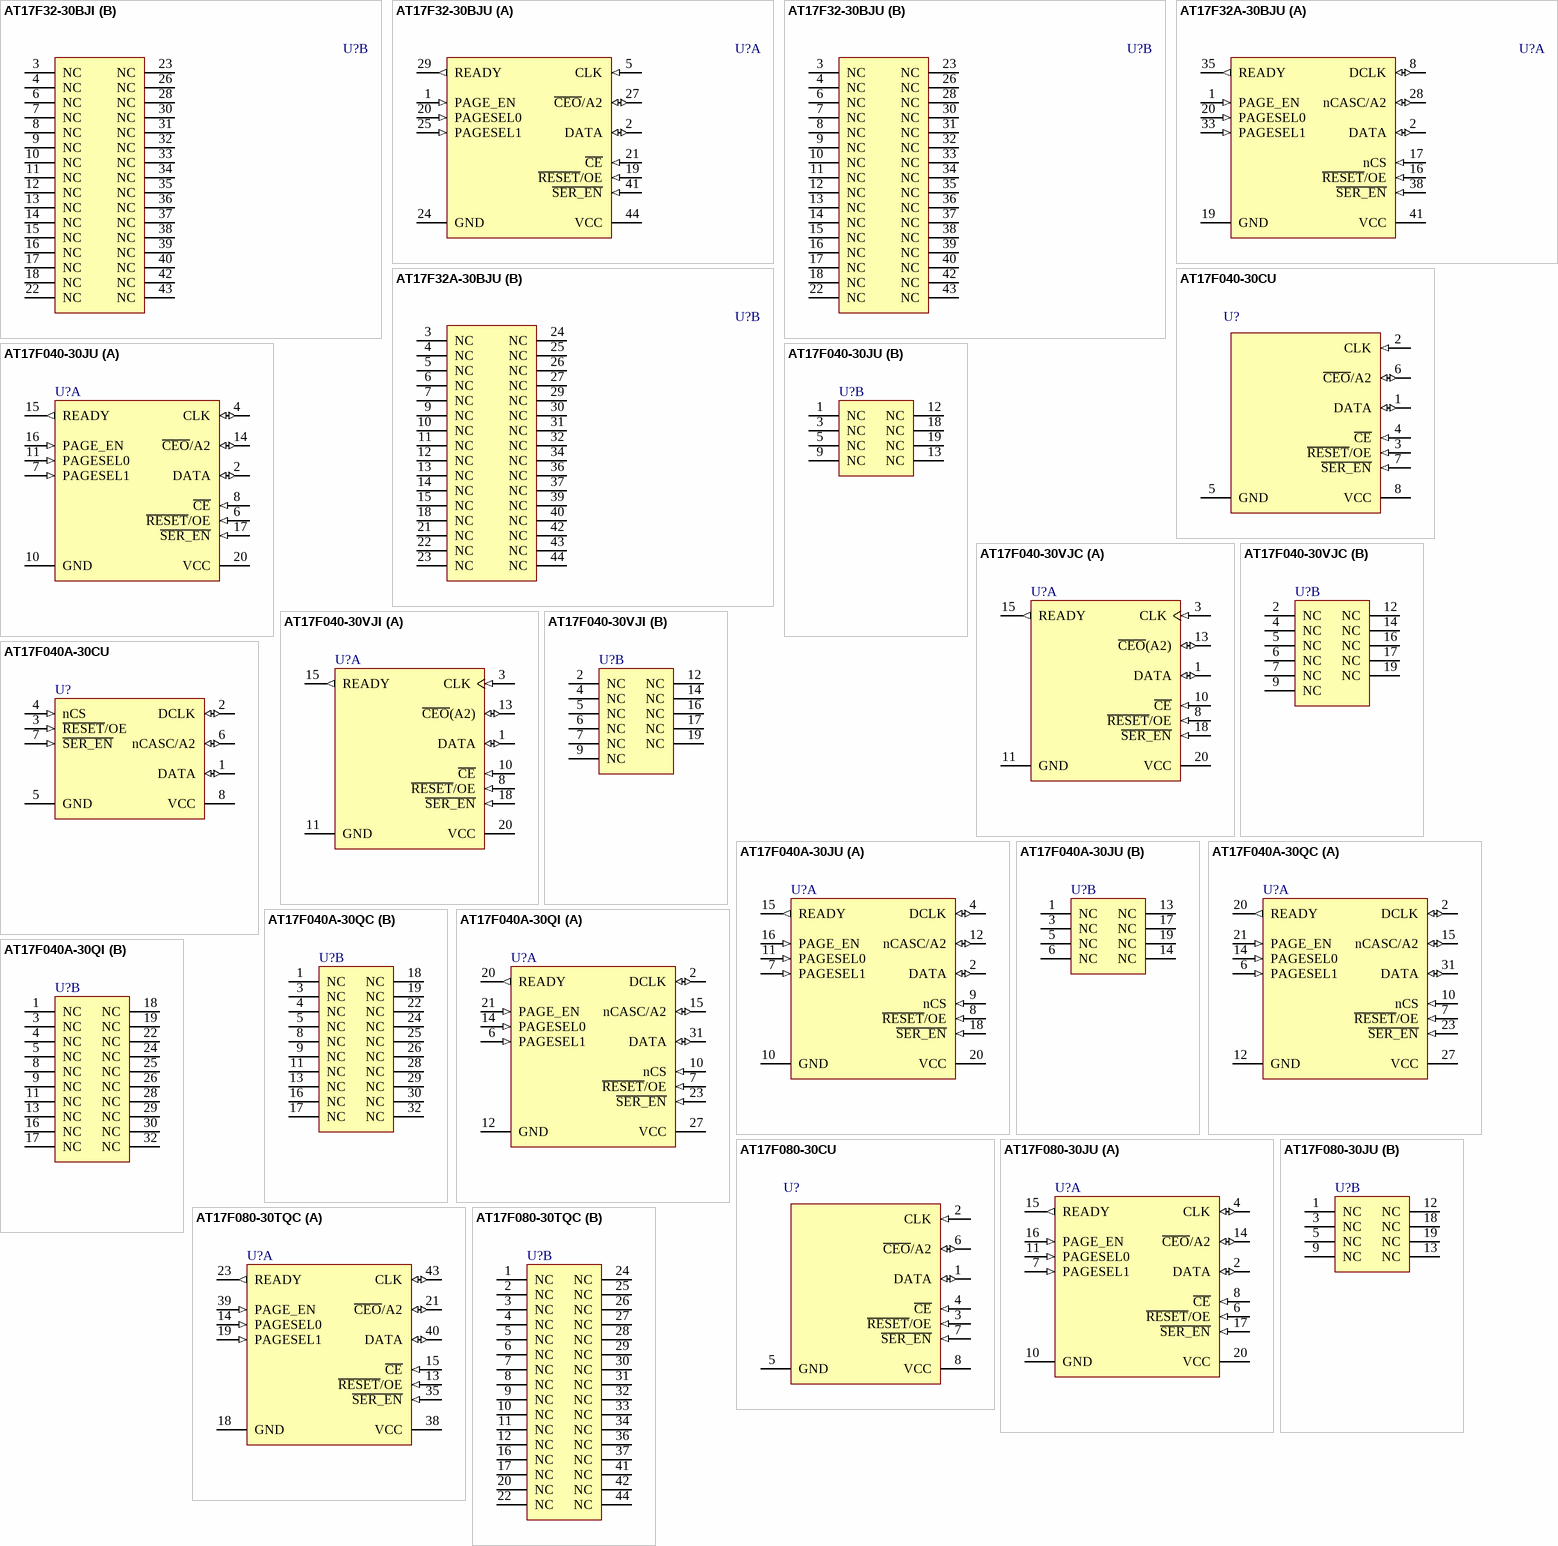
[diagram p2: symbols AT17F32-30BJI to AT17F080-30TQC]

## AT17F32-30BJI
designator U?
FPGA Configuration Flash Memory, 32-MBit Memory, 44-Pin PLCC, Industrial Grade
footprint 44J_N (Leaded Chip Carrier, 44-Leads, Body 16.6x16.6mm, Pitch 1.27mm, IPC Medium Density)
footprint 44J_L (Leaded Chip Carrier, 44-Leads, Body 16.6x16.6mm, Pitch 1.27mm, IPC High Density)
footprint 44J_M (Leaded Chip Carrier, 44-Leads, Body 16.6x16.6mm, Pitch 1.27mm, IPC Low Density)
part A pins: 1 PAGE_EN (in), 2 DATA (io), 5 CLK (in), 19 ~{RESET}/OE (in), 20 PAGESEL0 (in), 21 ~{CE} (in), 24 GND (power), 25 PAGESEL1 (in), 27 ~{CEO}/A2 (io), 29 READY (out), 41 ~{SER_EN} (in), 44 VCC (power)
part B pins: 3 NC, 4 NC, 6 NC, 7 NC, 8 NC, 9 NC, 10 NC, 11 NC, 12 NC, 13 NC, 14 NC, 15 NC, 16 NC, 17 NC, 18 NC, 22 NC, 23 NC, 26 NC, 28 NC, 30 NC, 31 NC, 32 NC, 33 NC, 34 NC, 35 NC, 36 NC, 37 NC, 38 NC, 39 NC, 40 NC, 42 NC, 43 NC

## AT17F32-30BJU
designator U?
FPGA Configuration Flash Memory, 32-MBit Memory, 44-Pin PLCC, LHF Industrial Grade
footprint 44J_N (Leaded Chip Carrier, 44-Leads, Body 16.6x16.6mm, Pitch 1.27mm, IPC Medium Density)
footprint 44J_L (Leaded Chip Carrier, 44-Leads, Body 16.6x16.6mm, Pitch 1.27mm, IPC High Density)
footprint 44J_M (Leaded Chip Carrier, 44-Leads, Body 16.6x16.6mm, Pitch 1.27mm, IPC Low Density)
part A pins: 1 PAGE_EN (in), 2 DATA (io), 5 CLK (in), 19 ~{RESET}/OE (in), 20 PAGESEL0 (in), 21 ~{CE} (in), 24 GND (power), 25 PAGESEL1 (in), 27 ~{CEO}/A2 (io), 29 READY (out), 41 ~{SER_EN} (in), 44 VCC (power)
part B pins: 3 NC, 4 NC, 6 NC, 7 NC, 8 NC, 9 NC, 10 NC, 11 NC, 12 NC, 13 NC, 14 NC, 15 NC, 16 NC, 17 NC, 18 NC, 22 NC, 23 NC, 26 NC, 28 NC, 30 NC, 31 NC, 32 NC, 33 NC, 34 NC, 35 NC, 36 NC, 37 NC, 38 NC, 39 NC, 40 NC, 42 NC, 43 NC

## AT17F32A-30BJU
designator U?
FPGA Configuration EEPROM 32-MBit Memory, 44-Pin PLCC, LHF Industrial Grade (-40°C to 85°C)
footprint 44J_N (Leaded Chip Carrier, 44-Leads, Body 16.6x16.6mm, Pitch 1.27mm, IPC Medium Density)
footprint 44J_L (Leaded Chip Carrier, 44-Leads, Body 16.6x16.6mm, Pitch 1.27mm, IPC High Density)
footprint 44J_M (Leaded Chip Carrier, 44-Leads, Body 16.6x16.6mm, Pitch 1.27mm, IPC Low Density)
part A pins: 1 PAGE_EN (in), 2 DATA (io), 8 DCLK (io), 16 ~{RESET}/OE (in), 17 nCS (in), 19 GND (power), 20 PAGESEL0 (in), 28 nCASC/A2 (io), 33 PAGESEL1 (in), 35 READY (out), 38 ~{SER_EN} (in), 41 VCC (power)
part B pins: 3 NC, 4 NC, 5 NC, 6 NC, 7 NC, 9 NC, 10 NC, 11 NC, 12 NC, 13 NC, 14 NC, 15 NC, 18 NC, 21 NC, 22 NC, 23 NC, 24 NC, 25 NC, 26 NC, 27 NC, 29 NC, 30 NC, 31 NC, 32 NC, 34 NC, 36 NC, 37 NC, 39 NC, 40 NC, 42 NC, 43 NC, 44 NC

## AT17F040-30CU
designator U?
FPGA Configuration Flash Memory, 4-MBit Memory, 8-Pin LAP, Industrial Grade (-40°C to 85°C), Pb-Free
footprint 8CN4 (SON, 8-Leads, Body 6x6 mm, Pitch 1.27mm)
pins: 1 DATA (io), 2 CLK (in), 3 ~{RESET}/OE (in), 4 ~{CE} (in), 5 GND (power), 6 ~{CEO}/A2 (io), 7 ~{SER_EN} (in), 8 VCC (power)

## AT17F040-30JU
designator U?
FPGA Configuration Flash Memory, 4-MBit Memory, 20-Pin PLCC, Industrial Grade (-40°C to 85°C), Pb-Free
footprint 20J_N (Leaded Chip Carrier, 20-Leads, Body 9x9mm, Pitch 1.27mm, IPC Medium Density)
footprint 20J_L (Leaded Chip Carrier, 20-Leads, Body 9x9mm, Pitch 1.27mm, IPC High Density)
footprint 20J_M (Leaded Chip Carrier, 20-Leads, Body 9x9mm, Pitch 1.27mm, IPC Low Density)
part A pins: 2 DATA (io), 4 CLK (io), 6 ~{RESET}/OE (in), 7 PAGESEL1 (in), 8 ~{CE} (in), 10 GND (power), 11 PAGESEL0 (in), 14 ~{CEO}/A2 (io), 15 READY (out), 16 PAGE_EN (in), 17 ~{SER_EN} (in), 20 VCC (power)
part B pins: 1 NC, 3 NC, 5 NC, 9 NC, 12 NC, 13 NC, 18 NC, 19 NC

## AT17F040-30VJC
designator U?
FPGA Configuration Flash Memory, 4-MBit Memory, 20-Pin PLCC, Commercial Grade (0°C to 70°C)
footprint 20J_N (Leaded Chip Carrier, 20-Leads, Body 9x9mm, Pitch 1.27mm, IPC Medium Density)
footprint 20J_L (Leaded Chip Carrier, 20-Leads, Body 9x9mm, Pitch 1.27mm, IPC High Density)
footprint 20J_M (Leaded Chip Carrier, 20-Leads, Body 9x9mm, Pitch 1.27mm, IPC Low Density)
part A pins: 1 DATA (io), 3 CLK (in), 8 ~{RESET}/OE (in), 10 ~{CE} (in), 11 GND (power), 13 ~{CEO}(A2) (io), 15 READY (out), 18 ~{SER_EN} (in), 20 VCC (power)
part B pins: 2 NC, 4 NC, 5 NC, 6 NC, 7 NC, 9 NC, 12 NC, 14 NC, 16 NC, 17 NC, 19 NC

## AT17F040-30VJI
designator U?
FPGA Configuration Flash Memory, 4-MBit Memory, 20-Pin PLCC, Industrial Grade (-40°C to 85°C)
footprint 20J_N (Leaded Chip Carrier, 20-Leads, Body 9x9mm, Pitch 1.27mm, IPC Medium Density)
footprint 20J_L (Leaded Chip Carrier, 20-Leads, Body 9x9mm, Pitch 1.27mm, IPC High Density)
footprint 20J_M (Leaded Chip Carrier, 20-Leads, Body 9x9mm, Pitch 1.27mm, IPC Low Density)
part A pins: 1 DATA (io), 3 CLK (in), 8 ~{RESET}/OE (in), 10 ~{CE} (in), 11 GND (power), 13 ~{CEO}(A2) (io), 15 READY (out), 18 ~{SER_EN} (in), 20 VCC (power)
part B pins: 2 NC, 4 NC, 5 NC, 6 NC, 7 NC, 9 NC, 12 NC, 14 NC, 16 NC, 17 NC, 19 NC

## AT17F040A-30CU
designator U?
FPGA Configuration Flash Memory, 4-MBit Memory, 8-Pin LAP, Industrial Grade (-40° C to 85° C), Pb-Free
footprint 8CN4 (SON, 8-Leads, Body 6x6 mm, Pitch 1.27mm)
pins: 1 DATA (io), 2 DCLK (io), 3 ~{RESET}/OE (in), 4 nCS (in), 5 GND (power), 6 nCASC/A2 (io), 7 ~{SER_EN} (in), 8 VCC (power)

## AT17F040A-30JU
designator U?
FPGA Configuration Flash Memory, 4-MBit Memory, 20-Pin PLCC, Industrial Grade (-40° C to 85° C), Pb-Free
footprint 20J_N (Leaded Chip Carrier, 20-Leads, Body 9x9mm, Pitch 1.27mm, IPC Medium Density)
footprint 20J_L (Leaded Chip Carrier, 20-Leads, Body 9x9mm, Pitch 1.27mm, IPC High Density)
footprint 20J_M (Leaded Chip Carrier, 20-Leads, Body 9x9mm, Pitch 1.27mm, IPC Low Density)
part A pins: 2 DATA (io), 4 DCLK (io), 7 PAGESEL1 (in), 8 ~{RESET}/OE (in), 9 nCS (in), 10 GND (power), 11 PAGESEL0 (in), 12 nCASC/A2 (io), 15 READY (out), 16 PAGE_EN (in), 18 ~{SER_EN} (in), 20 VCC (power)
part B pins: 1 NC, 3 NC, 5 NC, 6 NC, 13 NC, 14 NC, 17 NC, 19 NC

## AT17F040A-30QC
designator U?
FPGA Configuration Flash Memory, 4-MBit Memory, 32-Pin TQFP, Commercial Grade (0°C to 70°C)
footprint 32A_N (Thin QFP, 32-Leads, Body 7x7mm, Pitch 0.8mm, IPC Medium Density)
footprint 32A_L (Thin QFP, 32-Leads, Body 7x7mm, Pitch 0.8mm, IPC High Density)
footprint 32A_M (Thin QFP, 32-Leads, Body 7x7mm, Pitch 0.8mm, IPC Low Density)
part A pins: 2 DCLK (io), 6 PAGESEL1 (in), 7 ~{RESET}/OE (in), 10 nCS (in), 12 GND (power), 14 PAGESEL0 (in), 15 nCASC/A2 (io), 20 READY (out), 21 PAGE_EN (in), 23 ~{SER_EN} (in), 27 VCC (power), 31 DATA (io)
part B pins: 1 NC, 3 NC, 4 NC, 5 NC, 8 NC, 9 NC, 11 NC, 13 NC, 16 NC, 17 NC, 18 NC, 19 NC, 22 NC, 24 NC, 25 NC, 26 NC, 28 NC, 29 NC, 30 NC, 32 NC

## AT17F040A-30QI
designator U?
FPGA Configuration Flash Memory, 4-MBit Memory, 32-Pin TQFP, Industrial Grade (-40° C to 85° C)
footprint 32A_N (Thin QFP, 32-Leads, Body 7x7mm, Pitch 0.8mm, IPC Medium Density)
footprint 32A_L (Thin QFP, 32-Leads, Body 7x7mm, Pitch 0.8mm, IPC High Density)
footprint 32A_M (Thin QFP, 32-Leads, Body 7x7mm, Pitch 0.8mm, IPC Low Density)
part A pins: 2 DCLK (io), 6 PAGESEL1 (in), 7 ~{RESET}/OE (in), 10 nCS (in), 12 GND (power), 14 PAGESEL0 (in), 15 nCASC/A2 (io), 20 READY (out), 21 PAGE_EN (in), 23 ~{SER_EN} (in), 27 VCC (power), 31 DATA (io)
part B pins: 1 NC, 3 NC, 4 NC, 5 NC, 8 NC, 9 NC, 11 NC, 13 NC, 16 NC, 17 NC, 18 NC, 19 NC, 22 NC, 24 NC, 25 NC, 26 NC, 28 NC, 29 NC, 30 NC, 32 NC

## AT17F080-30CU
designator U?
FPGA Configuration Flash Memory, 8-MBit Memory, 8-Pin LAP, Industrial Grade (-40°C to 85°C), Pb-Free
footprint 8CN4 (SON, 8-Leads, Body 6x6 mm, Pitch 1.27mm)
pins: 1 DATA (io), 2 CLK (in), 3 ~{RESET}/OE (in), 4 ~{CE} (in), 5 GND (power), 6 ~{CEO}/A2 (io), 7 ~{SER_EN} (in), 8 VCC (power)

## AT17F080-30JU
designator U?
FPGA Configuration Flash Memory, 8-MBit Memory, 20-Pin PLCC, Industrial Grade (-40°C to 85°C), Pb-Free
footprint 20J_N (Leaded Chip Carrier, 20-Leads, Body 9x9mm, Pitch 1.27mm, IPC Medium Density)
footprint 20J_L (Leaded Chip Carrier, 20-Leads, Body 9x9mm, Pitch 1.27mm, IPC High Density)
footprint 20J_M (Leaded Chip Carrier, 20-Leads, Body 9x9mm, Pitch 1.27mm, IPC Low Density)
part A pins: 2 DATA (io), 4 CLK (io), 6 ~{RESET}/OE (in), 7 PAGESEL1 (in), 8 ~{CE} (in), 10 GND (power), 11 PAGESEL0 (in), 14 ~{CEO}/A2 (io), 15 READY (out), 16 PAGE_EN (in), 17 ~{SER_EN} (in), 20 VCC (power)
part B pins: 1 NC, 3 NC, 5 NC, 9 NC, 12 NC, 13 NC, 18 NC, 19 NC

## AT17F080-30TQC
designator U?
FPGA Configuration Flash Memory, 8-MBit Memory, 44-Pin TQFP, Commercial Grade (0°C to 70°C)
footprint 44A_N (Thin QFP, 44-Leads, Body 10x10mm, Pitch 0.8mm, IPC Medium Density)
footprint 44A_L (Thin QFP, 44-Leads, Body 10x10mm, Pitch 0.8mm, IPC High Density)
footprint 44A_M (Thin QFP, 44-Leads, Body 10x10mm, Pitch 0.8mm, IPC Low Density)
part A pins: 13 ~{RESET}/OE (in), 14 PAGESEL0 (in), 15 ~{CE} (in), 18 GND (power), 19 PAGESEL1 (in), 21 ~{CEO}/A2 (io), 23 READY (out), 35 ~{SER_EN} (in), 38 VCC (power), 39 PAGE_EN (in), 40 DATA (io), 43 CLK (io)
part B pins: 1 NC, 2 NC, 3 NC, 4 NC, 5 NC, 6 NC, 7 NC, 8 NC, 9 NC, 10 NC, 11 NC, 12 NC, 16 NC, 17 NC, 20 NC, 22 NC, 24 NC, 25 NC, 26 NC, 27 NC, 28 NC, 29 NC, 30 NC, 31 NC, 32 NC, 33 NC, 34 NC, 36 NC, 37 NC, 41 NC, 42 NC, 44 NC

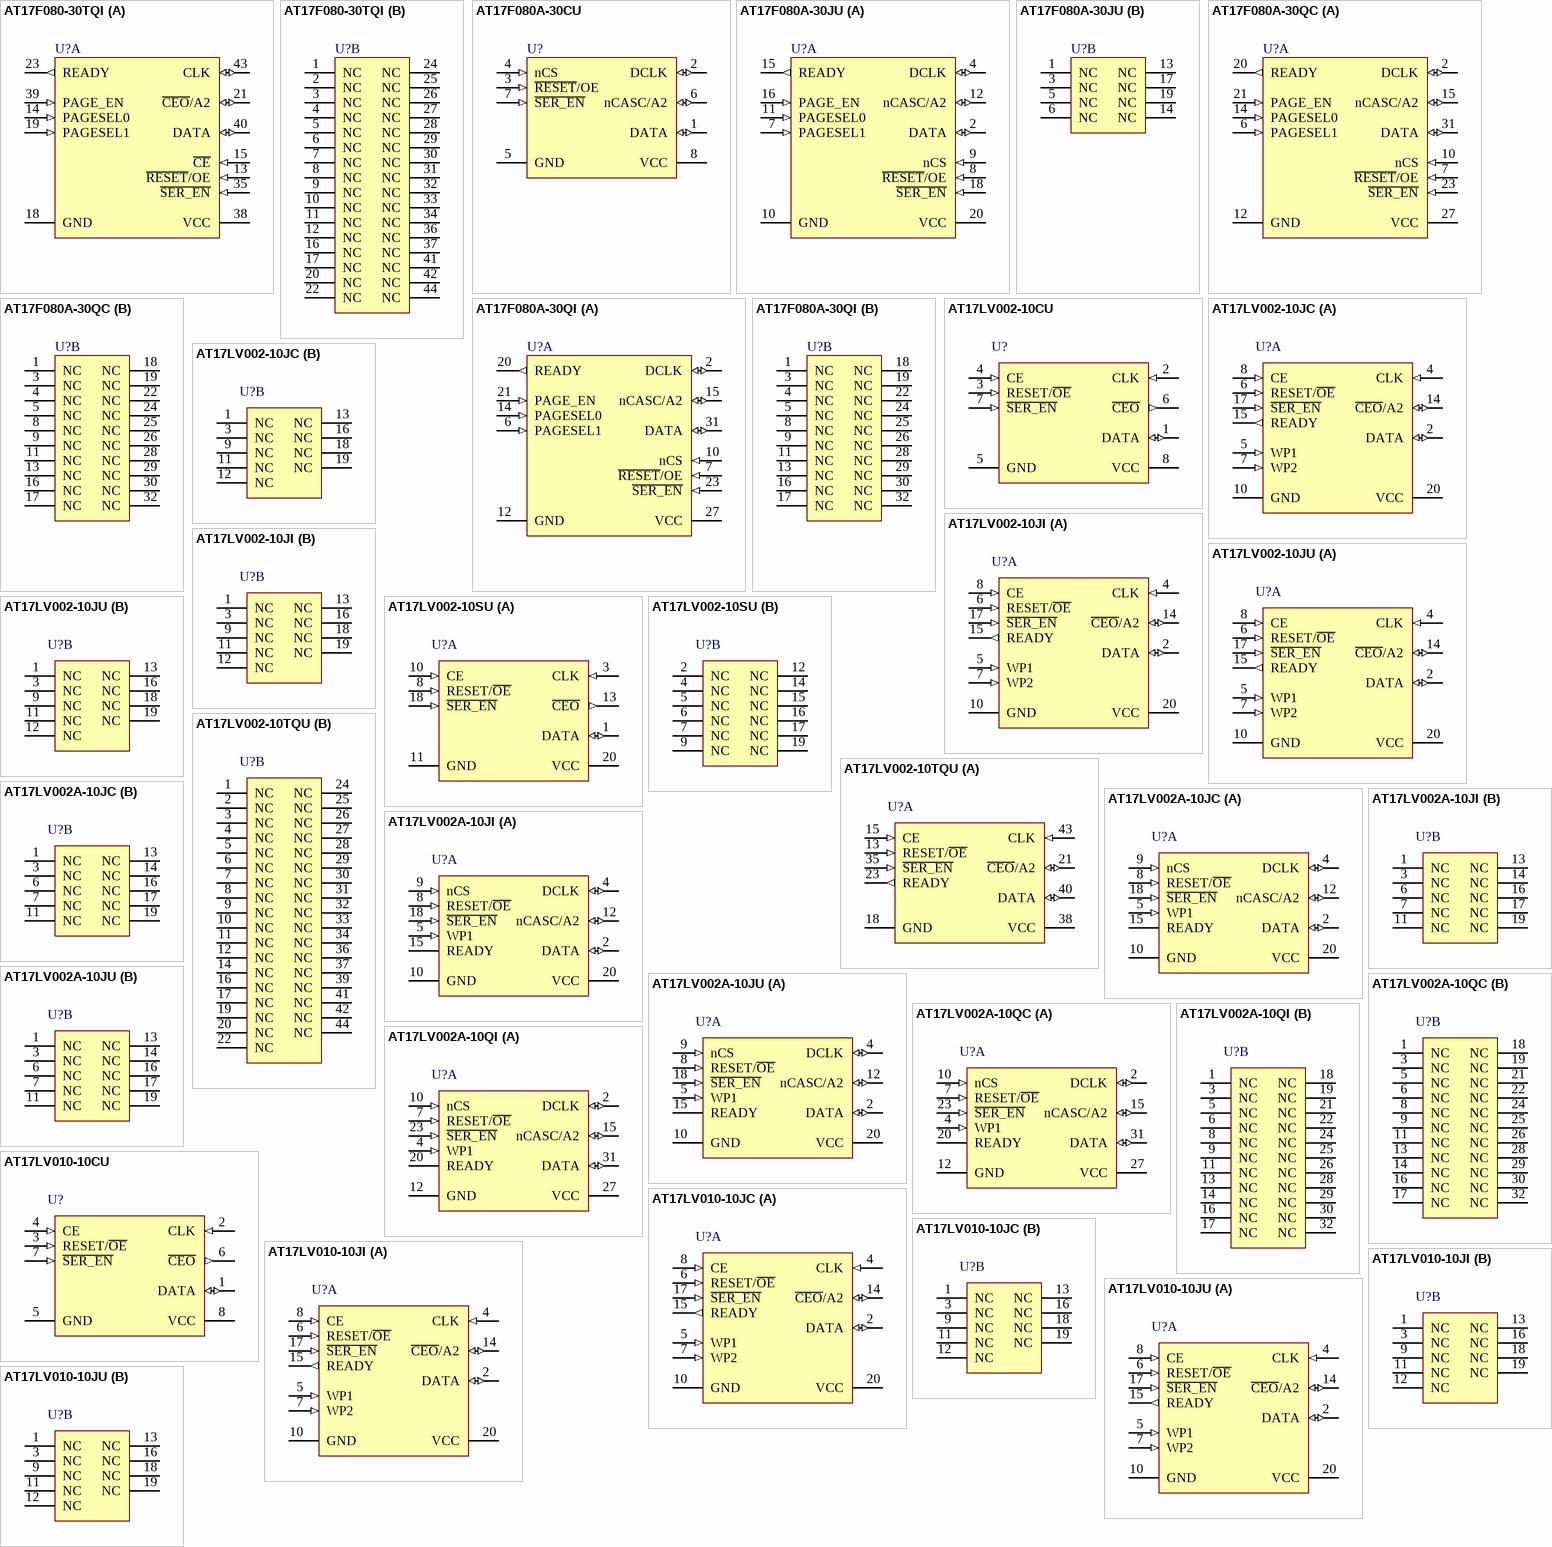
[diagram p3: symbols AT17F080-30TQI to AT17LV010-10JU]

## AT17F080-30TQI
designator U?
FPGA Configuration Flash Memory, 8-MBit Memory, 44-Pin TQFP, Industrial Grade (-40°C to 85°C)
footprint 44A_N (Thin QFP, 44-Leads, Body 10x10mm, Pitch 0.8mm, IPC Medium Density)
footprint 44A_L (Thin QFP, 44-Leads, Body 10x10mm, Pitch 0.8mm, IPC High Density)
footprint 44A_M (Thin QFP, 44-Leads, Body 10x10mm, Pitch 0.8mm, IPC Low Density)
part A pins: 13 ~{RESET}/OE (in), 14 PAGESEL0 (in), 15 ~{CE} (in), 18 GND (power), 19 PAGESEL1 (in), 21 ~{CEO}/A2 (io), 23 READY (out), 35 ~{SER_EN} (in), 38 VCC (power), 39 PAGE_EN (in), 40 DATA (io), 43 CLK (io)
part B pins: 1 NC, 2 NC, 3 NC, 4 NC, 5 NC, 6 NC, 7 NC, 8 NC, 9 NC, 10 NC, 11 NC, 12 NC, 16 NC, 17 NC, 20 NC, 22 NC, 24 NC, 25 NC, 26 NC, 27 NC, 28 NC, 29 NC, 30 NC, 31 NC, 32 NC, 33 NC, 34 NC, 36 NC, 37 NC, 41 NC, 42 NC, 44 NC

## AT17F080A-30CU
designator U?
FPGA Configuration Flash Memory, 8-MBit Memory, 8-Pin LAP, Industrial Grade (-40° C to 85° C), Pb-Free
footprint 8CN4 (SON, 8-Leads, Body 6x6 mm, Pitch 1.27mm)
pins: 1 DATA (io), 2 DCLK (io), 3 ~{RESET}/OE (in), 4 nCS (in), 5 GND (power), 6 nCASC/A2 (io), 7 ~{SER_EN} (in), 8 VCC (power)

## AT17F080A-30JU
designator U?
FPGA Configuration Flash Memory, 8-MBit Memory, 20-Pin PLCC, Industrial Grade (-40° C to 85° C), Pb-Free
footprint 20J_N (Leaded Chip Carrier, 20-Leads, Body 9x9mm, Pitch 1.27mm, IPC Medium Density)
footprint 20J_L (Leaded Chip Carrier, 20-Leads, Body 9x9mm, Pitch 1.27mm, IPC High Density)
footprint 20J_M (Leaded Chip Carrier, 20-Leads, Body 9x9mm, Pitch 1.27mm, IPC Low Density)
part A pins: 2 DATA (io), 4 DCLK (io), 7 PAGESEL1 (in), 8 ~{RESET}/OE (in), 9 nCS (in), 10 GND (power), 11 PAGESEL0 (in), 12 nCASC/A2 (io), 15 READY (out), 16 PAGE_EN (in), 18 ~{SER_EN} (in), 20 VCC (power)
part B pins: 1 NC, 3 NC, 5 NC, 6 NC, 13 NC, 14 NC, 17 NC, 19 NC

## AT17F080A-30QC
designator U?
FPGA Configuration Flash Memory, 8-MBit Memory, 32-Pin TQFP, Commercial Grade (0°C to 70°C)
footprint 32A_N (Thin QFP, 32-Leads, Body 7x7mm, Pitch 0.8mm, IPC Medium Density)
footprint 32A_L (Thin QFP, 32-Leads, Body 7x7mm, Pitch 0.8mm, IPC High Density)
footprint 32A_M (Thin QFP, 32-Leads, Body 7x7mm, Pitch 0.8mm, IPC Low Density)
part A pins: 2 DCLK (io), 6 PAGESEL1 (in), 7 ~{RESET}/OE (in), 10 nCS (in), 12 GND (power), 14 PAGESEL0 (in), 15 nCASC/A2 (io), 20 READY (out), 21 PAGE_EN (in), 23 ~{SER_EN} (in), 27 VCC (power), 31 DATA (io)
part B pins: 1 NC, 3 NC, 4 NC, 5 NC, 8 NC, 9 NC, 11 NC, 13 NC, 16 NC, 17 NC, 18 NC, 19 NC, 22 NC, 24 NC, 25 NC, 26 NC, 28 NC, 29 NC, 30 NC, 32 NC

## AT17F080A-30QI
designator U?
FPGA Configuration Flash Memory, 8-MBit Memory, 32-Pin TQFP, Industrial Grade (-40° C to 85° C)
footprint 32A_N (Thin QFP, 32-Leads, Body 7x7mm, Pitch 0.8mm, IPC Medium Density)
footprint 32A_L (Thin QFP, 32-Leads, Body 7x7mm, Pitch 0.8mm, IPC High Density)
footprint 32A_M (Thin QFP, 32-Leads, Body 7x7mm, Pitch 0.8mm, IPC Low Density)
part A pins: 2 DCLK (io), 6 PAGESEL1 (in), 7 ~{RESET}/OE (in), 10 nCS (in), 12 GND (power), 14 PAGESEL0 (in), 15 nCASC/A2 (io), 20 READY (out), 21 PAGE_EN (in), 23 ~{SER_EN} (in), 27 VCC (power), 31 DATA (io)
part B pins: 1 NC, 3 NC, 4 NC, 5 NC, 8 NC, 9 NC, 11 NC, 13 NC, 16 NC, 17 NC, 18 NC, 19 NC, 22 NC, 24 NC, 25 NC, 26 NC, 28 NC, 29 NC, 30 NC, 32 NC

## AT17LV002-10CU
designator U?
FPGA Configuration EEPROM Memory, 2-MBit Memory, 8-Pin LAP, Industrial Grade (-40°C to 85°C), Pb-Free
footprint 8CN4 (SON, 8-Leads, Body 6x6 mm, Pitch 1.27mm)
pins: 1 DATA (io), 2 CLK (in), 3 RESET/~{OE} (in), 4 CE (in), 5 GND (power), 6 ~{CEO} (out), 7 ~{SER_EN} (in), 8 VCC (power)

## AT17LV002-10JC
designator U?
FPGA Configuration EEPROM Memory, 2-MBit Memory, 20-Pin PLCC, Commercial Grade (0°C to 70°C)
footprint 20J_N (Leaded Chip Carrier, 20-Leads, Body 9x9mm, Pitch 1.27mm, IPC Medium Density)
footprint 20J_L (Leaded Chip Carrier, 20-Leads, Body 9x9mm, Pitch 1.27mm, IPC High Density)
footprint 20J_M (Leaded Chip Carrier, 20-Leads, Body 9x9mm, Pitch 1.27mm, IPC Low Density)
part A pins: 2 DATA (io), 4 CLK (in), 5 WP1 (in), 6 RESET/~{OE} (in), 7 WP2 (in), 8 CE (in), 10 GND (power), 14 ~{CEO}/A2 (io), 15 READY (out), 17 ~{SER_EN} (in), 20 VCC (power)
part B pins: 1 NC, 3 NC, 9 NC, 11 NC, 12 NC, 13 NC, 16 NC, 18 NC, 19 NC

## AT17LV002-10JI
designator U?
FPGA Configuration EEPROM Memory, 2-MBit Memory, 20-Pin PLCC, Industrial Grade (-40°C to 85°C)
footprint 20J_N (Leaded Chip Carrier, 20-Leads, Body 9x9mm, Pitch 1.27mm, IPC Medium Density)
footprint 20J_L (Leaded Chip Carrier, 20-Leads, Body 9x9mm, Pitch 1.27mm, IPC High Density)
footprint 20J_M (Leaded Chip Carrier, 20-Leads, Body 9x9mm, Pitch 1.27mm, IPC Low Density)
part A pins: 2 DATA (io), 4 CLK (in), 5 WP1 (in), 6 RESET/~{OE} (in), 7 WP2 (in), 8 CE (in), 10 GND (power), 14 ~{CEO}/A2 (io), 15 READY (out), 17 ~{SER_EN} (in), 20 VCC (power)
part B pins: 1 NC, 3 NC, 9 NC, 11 NC, 12 NC, 13 NC, 16 NC, 18 NC, 19 NC

## AT17LV002-10JU
designator U?
FPGA Configuration EEPROM Memory, 2-MBit Memory, 20-Pin PLCC, Industrial Grade (-40°C to 85°C), Pb-Free
footprint 20J_N (Leaded Chip Carrier, 20-Leads, Body 9x9mm, Pitch 1.27mm, IPC Medium Density)
footprint 20J_L (Leaded Chip Carrier, 20-Leads, Body 9x9mm, Pitch 1.27mm, IPC High Density)
footprint 20J_M (Leaded Chip Carrier, 20-Leads, Body 9x9mm, Pitch 1.27mm, IPC Low Density)
part A pins: 2 DATA (io), 4 CLK (in), 5 WP1 (in), 6 RESET/~{OE} (in), 7 WP2 (in), 8 CE (in), 10 GND (power), 14 ~{CEO}/A2 (io), 15 READY (out), 17 ~{SER_EN} (in), 20 VCC (power)
part B pins: 1 NC, 3 NC, 9 NC, 11 NC, 12 NC, 13 NC, 16 NC, 18 NC, 19 NC

## AT17LV002-10SU
designator U?
FPGA Configuration EEPROM Memory, 2-MBit Memory, 20-Pin SOIC, Industrial Grade (-40°C to 85°C), Pb-Free
footprint 20S2_N (SOIC, 20-Leads, Body 12.8x7.5mm, Pitch 1.27mm, IPC Medium Density)
footprint 20S2_L (SOIC, 20-Leads, Body 12.8x7.5mm, Pitch 1.27mm, IPC High Density)
footprint 20S2_M (SOIC, 20-Leads, Body 12.8x7.5mm, Pitch 1.27mm, IPC Low Density)
part A pins: 1 DATA (io), 3 CLK (in), 8 RESET/~{OE} (in), 10 CE (in), 11 GND (power), 13 ~{CEO} (out), 18 ~{SER_EN} (in), 20 VCC (power)
part B pins: 2 NC, 4 NC, 5 NC, 6 NC, 7 NC, 9 NC, 12 NC, 14 NC, 15 NC, 16 NC, 17 NC, 19 NC

## AT17LV002-10TQU
designator U?
FPGA Configuration EEPROM Memory, 2-MBit Memory, 44-Pin TQFP, Industrial Grade (-40°C to 85°C), Pb-Free
footprint 44A_N (Thin QFP, 44-Leads, Body 10x10mm, Pitch 0.8mm, IPC Medium Density)
footprint 44A_L (Thin QFP, 44-Leads, Body 10x10mm, Pitch 0.8mm, IPC High Density)
footprint 44A_M (Thin QFP, 44-Leads, Body 10x10mm, Pitch 0.8mm, IPC Low Density)
part A pins: 13 RESET/~{OE} (in), 15 CE (in), 18 GND (power), 21 ~{CEO}/A2 (io), 23 READY (out), 35 ~{SER_EN} (in), 38 VCC (power), 40 DATA (io), 43 CLK (in)
part B pins: 1 NC, 2 NC, 3 NC, 4 NC, 5 NC, 6 NC, 7 NC, 8 NC, 9 NC, 10 NC, 11 NC, 12 NC, 14 NC, 16 NC, 17 NC, 19 NC, 20 NC, 22 NC, 24 NC, 25 NC, 26 NC, 27 NC, 28 NC, 29 NC, 30 NC, 31 NC, 32 NC, 33 NC, 34 NC, 36 NC, 37 NC, 39 NC, 41 NC, 42 NC, 44 NC

## AT17LV002A-10JC
designator U?
FPGA Configuration EEPROM Memory, 2-MBit Memory, 20-Pin PLCC, Commercial Grade (0°C to 70°C)
footprint 20J_N (Leaded Chip Carrier, 20-Leads, Body 9x9mm, Pitch 1.27mm, IPC Medium Density)
footprint 20J_L (Leaded Chip Carrier, 20-Leads, Body 9x9mm, Pitch 1.27mm, IPC High Density)
footprint 20J_M (Leaded Chip Carrier, 20-Leads, Body 9x9mm, Pitch 1.27mm, IPC Low Density)
part A pins: 2 DATA (io), 4 DCLK (io), 5 WP1 (in), 8 RESET/~{OE} (in), 9 nCS (in), 10 GND (power), 12 nCASC/A2 (io), 15 READY (oc), 18 ~{SER_EN} (in), 20 VCC (power)
part B pins: 1 NC, 3 NC, 6 NC, 7 NC, 11 NC, 13 NC, 14 NC, 16 NC, 17 NC, 19 NC

## AT17LV002A-10JI
designator U?
FPGA Configuration EEPROM Memory, 2-MBit Memory, 20-Pin PLCC, Industrial Grade (-40°C to 85°C)
footprint 20J_N (Leaded Chip Carrier, 20-Leads, Body 9x9mm, Pitch 1.27mm, IPC Medium Density)
footprint 20J_L (Leaded Chip Carrier, 20-Leads, Body 9x9mm, Pitch 1.27mm, IPC High Density)
footprint 20J_M (Leaded Chip Carrier, 20-Leads, Body 9x9mm, Pitch 1.27mm, IPC Low Density)
part A pins: 2 DATA (io), 4 DCLK (io), 5 WP1 (in), 8 RESET/~{OE} (in), 9 nCS (in), 10 GND (power), 12 nCASC/A2 (io), 15 READY (oc), 18 ~{SER_EN} (in), 20 VCC (power)
part B pins: 1 NC, 3 NC, 6 NC, 7 NC, 11 NC, 13 NC, 14 NC, 16 NC, 17 NC, 19 NC

## AT17LV002A-10JU
designator U?
FPGA Configuration EEPROM Memory, 2-MBit Memory, 20-Pin PLCC, Industrial Grade (-40°C to 85°C), Pb-Free
footprint 20J_N (Leaded Chip Carrier, 20-Leads, Body 9x9mm, Pitch 1.27mm, IPC Medium Density)
footprint 20J_L (Leaded Chip Carrier, 20-Leads, Body 9x9mm, Pitch 1.27mm, IPC High Density)
footprint 20J_M (Leaded Chip Carrier, 20-Leads, Body 9x9mm, Pitch 1.27mm, IPC Low Density)
part A pins: 2 DATA (io), 4 DCLK (io), 5 WP1 (in), 8 RESET/~{OE} (in), 9 nCS (in), 10 GND (power), 12 nCASC/A2 (io), 15 READY (oc), 18 ~{SER_EN} (in), 20 VCC (power)
part B pins: 1 NC, 3 NC, 6 NC, 7 NC, 11 NC, 13 NC, 14 NC, 16 NC, 17 NC, 19 NC

## AT17LV002A-10QC
designator U?
FPGA Configuration EEPROM Memory, 2-MBit Memory, 32-Pin TQFP, Commercial Grade (0°C to 70°C)
footprint 32A_N (Thin QFP, 32-Leads, Body 7x7mm, Pitch 0.8mm, IPC Medium Density)
footprint 32A_L (Thin QFP, 32-Leads, Body 7x7mm, Pitch 0.8mm, IPC High Density)
footprint 32A_M (Thin QFP, 32-Leads, Body 7x7mm, Pitch 0.8mm, IPC Low Density)
part A pins: 2 DCLK (io), 4 WP1 (in), 7 RESET/~{OE} (in), 10 nCS (in), 12 GND (power), 15 nCASC/A2 (io), 20 READY (oc), 23 ~{SER_EN} (in), 27 VCC (power), 31 DATA (io)
part B pins: 1 NC, 3 NC, 5 NC, 6 NC, 8 NC, 9 NC, 11 NC, 13 NC, 14 NC, 16 NC, 17 NC, 18 NC, 19 NC, 21 NC, 22 NC, 24 NC, 25 NC, 26 NC, 28 NC, 29 NC, 30 NC, 32 NC

## AT17LV002A-10QI
designator U?
FPGA Configuration EEPROM Memory, 2-MBit Memory, 32-Pin TQFP, Industrial Grade (-40°C to 85°C)
footprint 32A_N (Thin QFP, 32-Leads, Body 7x7mm, Pitch 0.8mm, IPC Medium Density)
footprint 32A_L (Thin QFP, 32-Leads, Body 7x7mm, Pitch 0.8mm, IPC High Density)
footprint 32A_M (Thin QFP, 32-Leads, Body 7x7mm, Pitch 0.8mm, IPC Low Density)
part A pins: 2 DCLK (io), 4 WP1 (in), 7 RESET/~{OE} (in), 10 nCS (in), 12 GND (power), 15 nCASC/A2 (io), 20 READY (oc), 23 ~{SER_EN} (in), 27 VCC (power), 31 DATA (io)
part B pins: 1 NC, 3 NC, 5 NC, 6 NC, 8 NC, 9 NC, 11 NC, 13 NC, 14 NC, 16 NC, 17 NC, 18 NC, 19 NC, 21 NC, 22 NC, 24 NC, 25 NC, 26 NC, 28 NC, 29 NC, 30 NC, 32 NC

## AT17LV010-10CU
designator U?
FPGA Configuration EEPROM Memory, 1-MBit Memory, 8-Pin LAP, Industrial Grade (-40°C to 85°C), Pb-Free
footprint 8CN4 (SON, 8-Leads, Body 6x6 mm, Pitch 1.27mm)
pins: 1 DATA (io), 2 CLK (in), 3 RESET/~{OE} (in), 4 CE (in), 5 GND (power), 6 ~{CEO} (out), 7 ~{SER_EN} (in), 8 VCC (power)

## AT17LV010-10JC
designator U?
FPGA Configuration EEPROM Memory, 1-MBit Memory, 20-Pin PLCC, Commercial Grade (0°C to 70°C)
footprint 20J_N (Leaded Chip Carrier, 20-Leads, Body 9x9mm, Pitch 1.27mm, IPC Medium Density)
footprint 20J_L (Leaded Chip Carrier, 20-Leads, Body 9x9mm, Pitch 1.27mm, IPC High Density)
footprint 20J_M (Leaded Chip Carrier, 20-Leads, Body 9x9mm, Pitch 1.27mm, IPC Low Density)
part A pins: 2 DATA (io), 4 CLK (in), 5 WP1 (in), 6 RESET/~{OE} (in), 7 WP2 (in), 8 CE (in), 10 GND (power), 14 ~{CEO}/A2 (io), 15 READY (out), 17 ~{SER_EN} (in), 20 VCC (power)
part B pins: 1 NC, 3 NC, 9 NC, 11 NC, 12 NC, 13 NC, 16 NC, 18 NC, 19 NC

## AT17LV010-10JI
designator U?
FPGA Configuration EEPROM Memory, 1-MBit Memory, 20-Pin PLCC, Industrial Grade (-40°C to 85°C)
footprint 20J_N (Leaded Chip Carrier, 20-Leads, Body 9x9mm, Pitch 1.27mm, IPC Medium Density)
footprint 20J_L (Leaded Chip Carrier, 20-Leads, Body 9x9mm, Pitch 1.27mm, IPC High Density)
footprint 20J_M (Leaded Chip Carrier, 20-Leads, Body 9x9mm, Pitch 1.27mm, IPC Low Density)
part A pins: 2 DATA (io), 4 CLK (in), 5 WP1 (in), 6 RESET/~{OE} (in), 7 WP2 (in), 8 CE (in), 10 GND (power), 14 ~{CEO}/A2 (io), 15 READY (out), 17 ~{SER_EN} (in), 20 VCC (power)
part B pins: 1 NC, 3 NC, 9 NC, 11 NC, 12 NC, 13 NC, 16 NC, 18 NC, 19 NC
